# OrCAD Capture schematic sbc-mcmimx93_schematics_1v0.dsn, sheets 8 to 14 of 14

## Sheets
8 09 Gbe: size C; title: SBC-MCM93   09. Ethernet
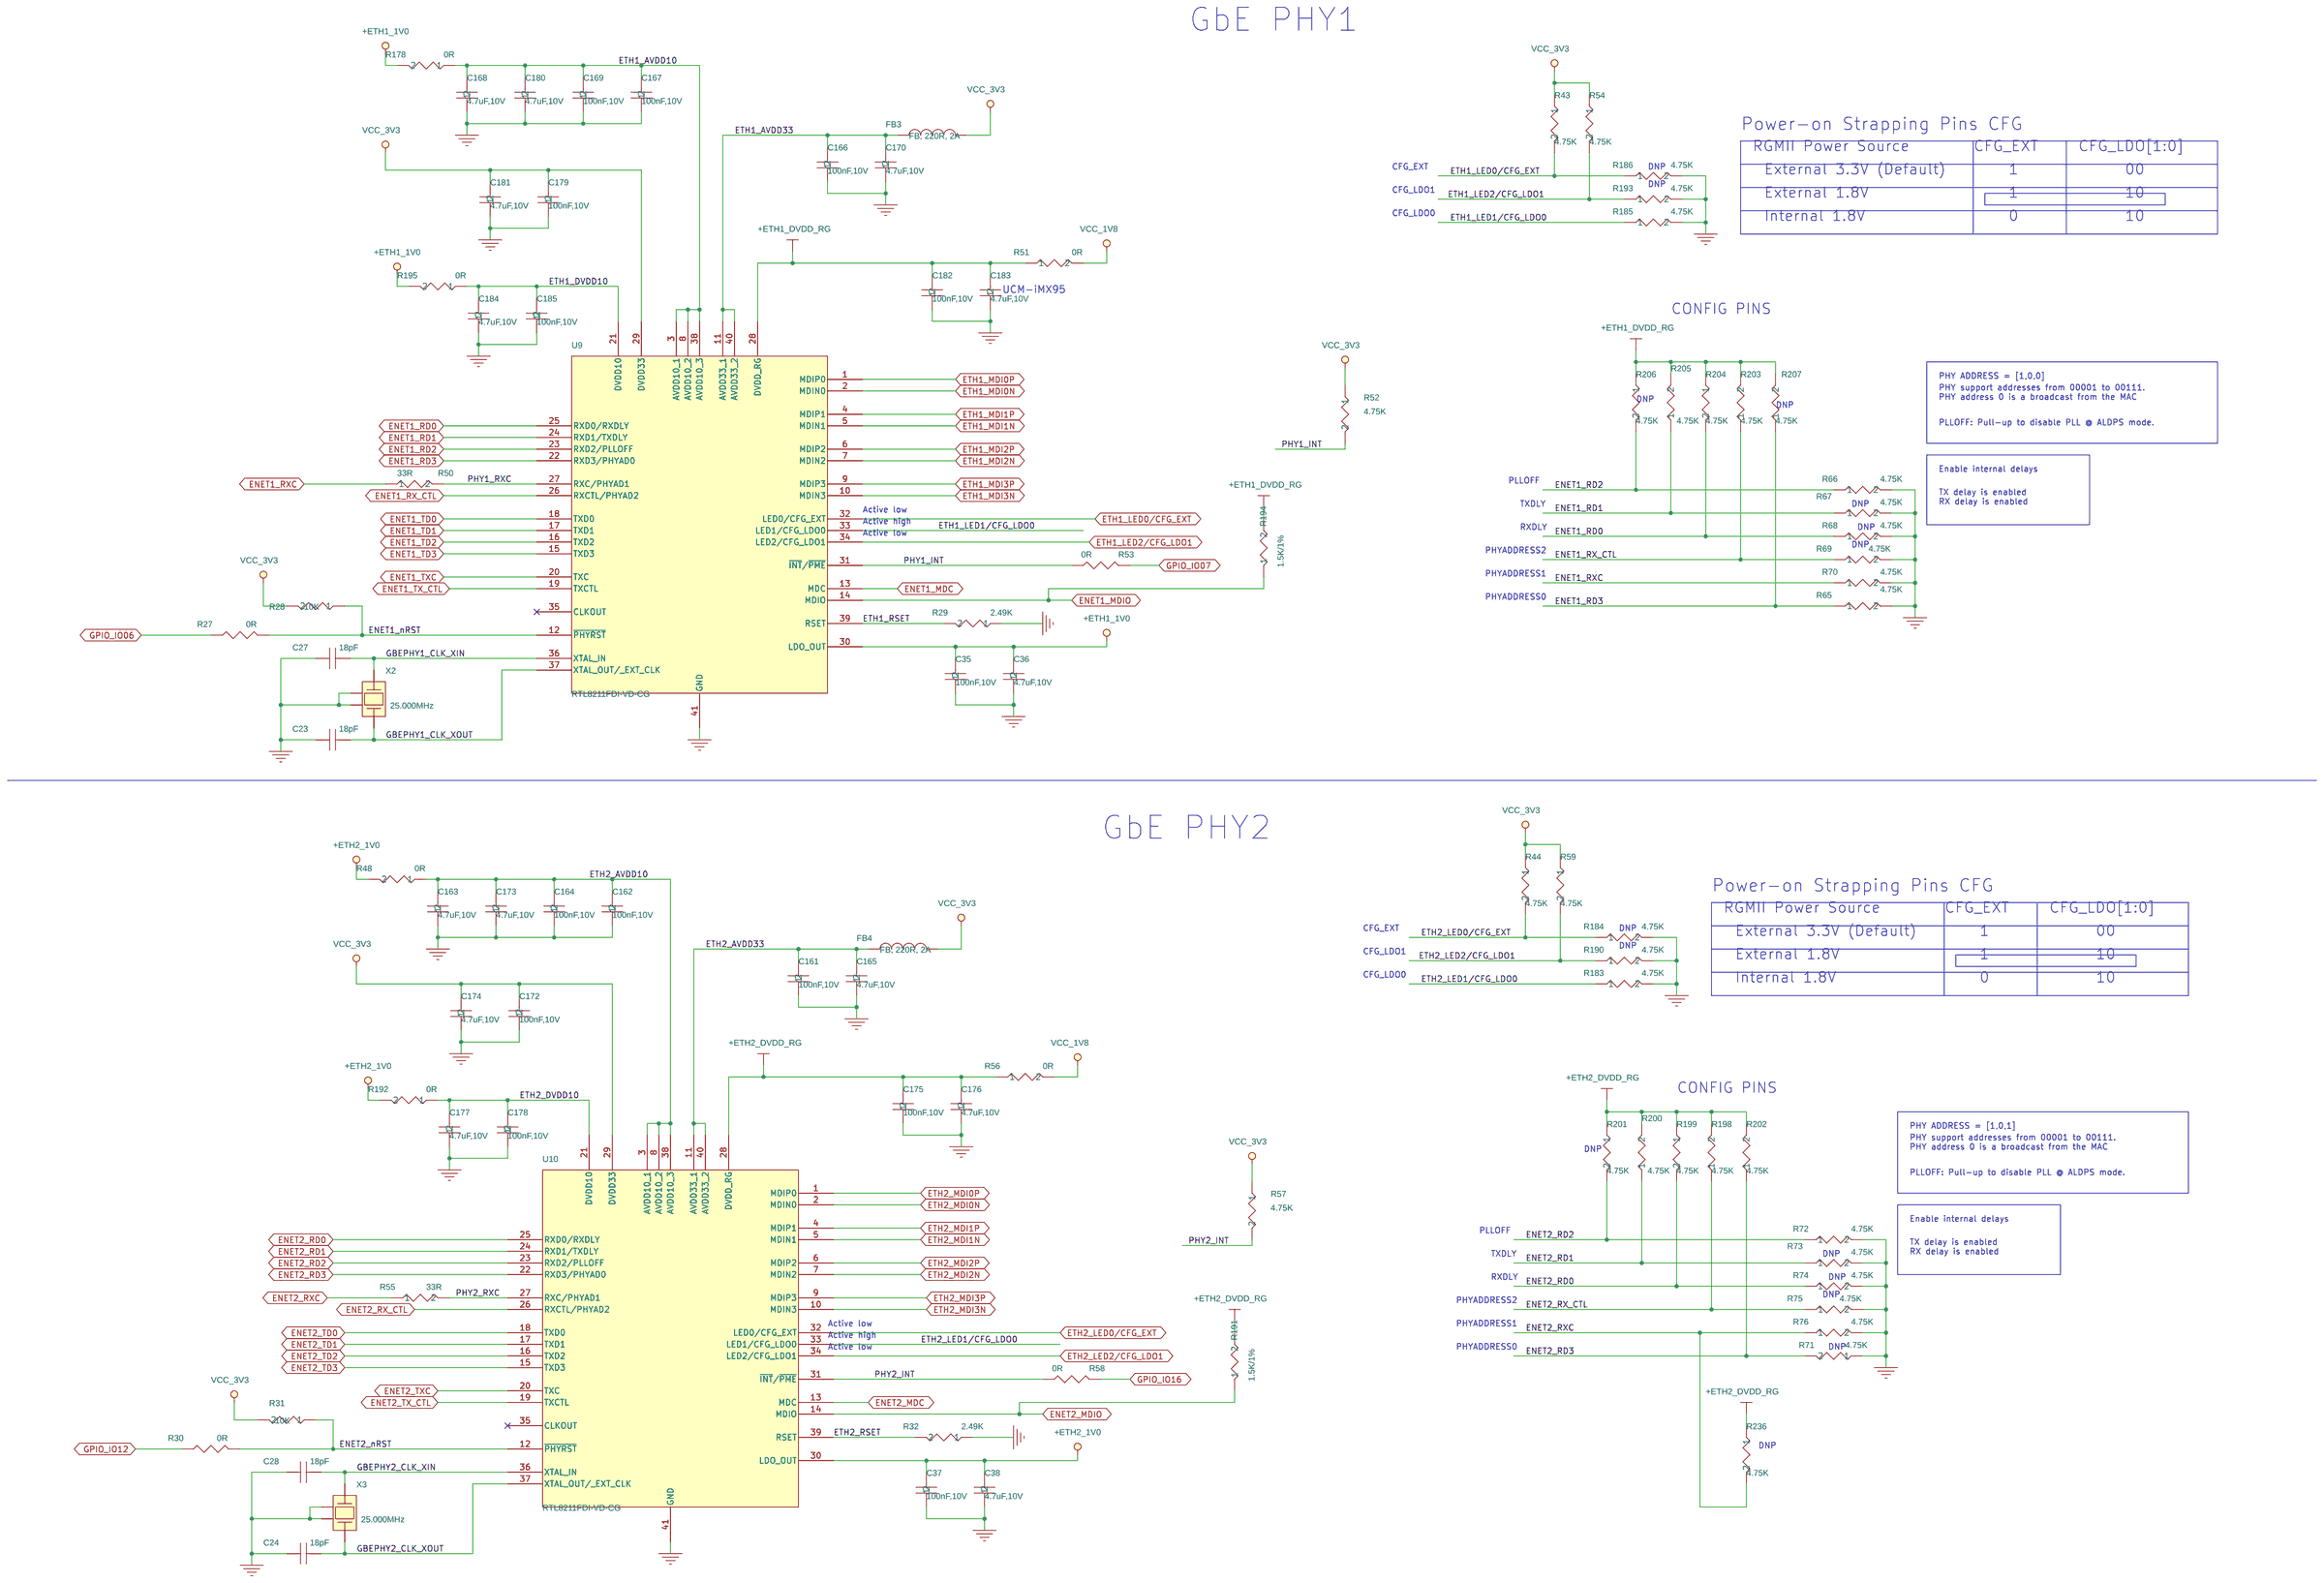
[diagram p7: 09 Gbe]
9 08 LVDS LCD: size B; title: SBC-MCM93   08. LVDS LCD
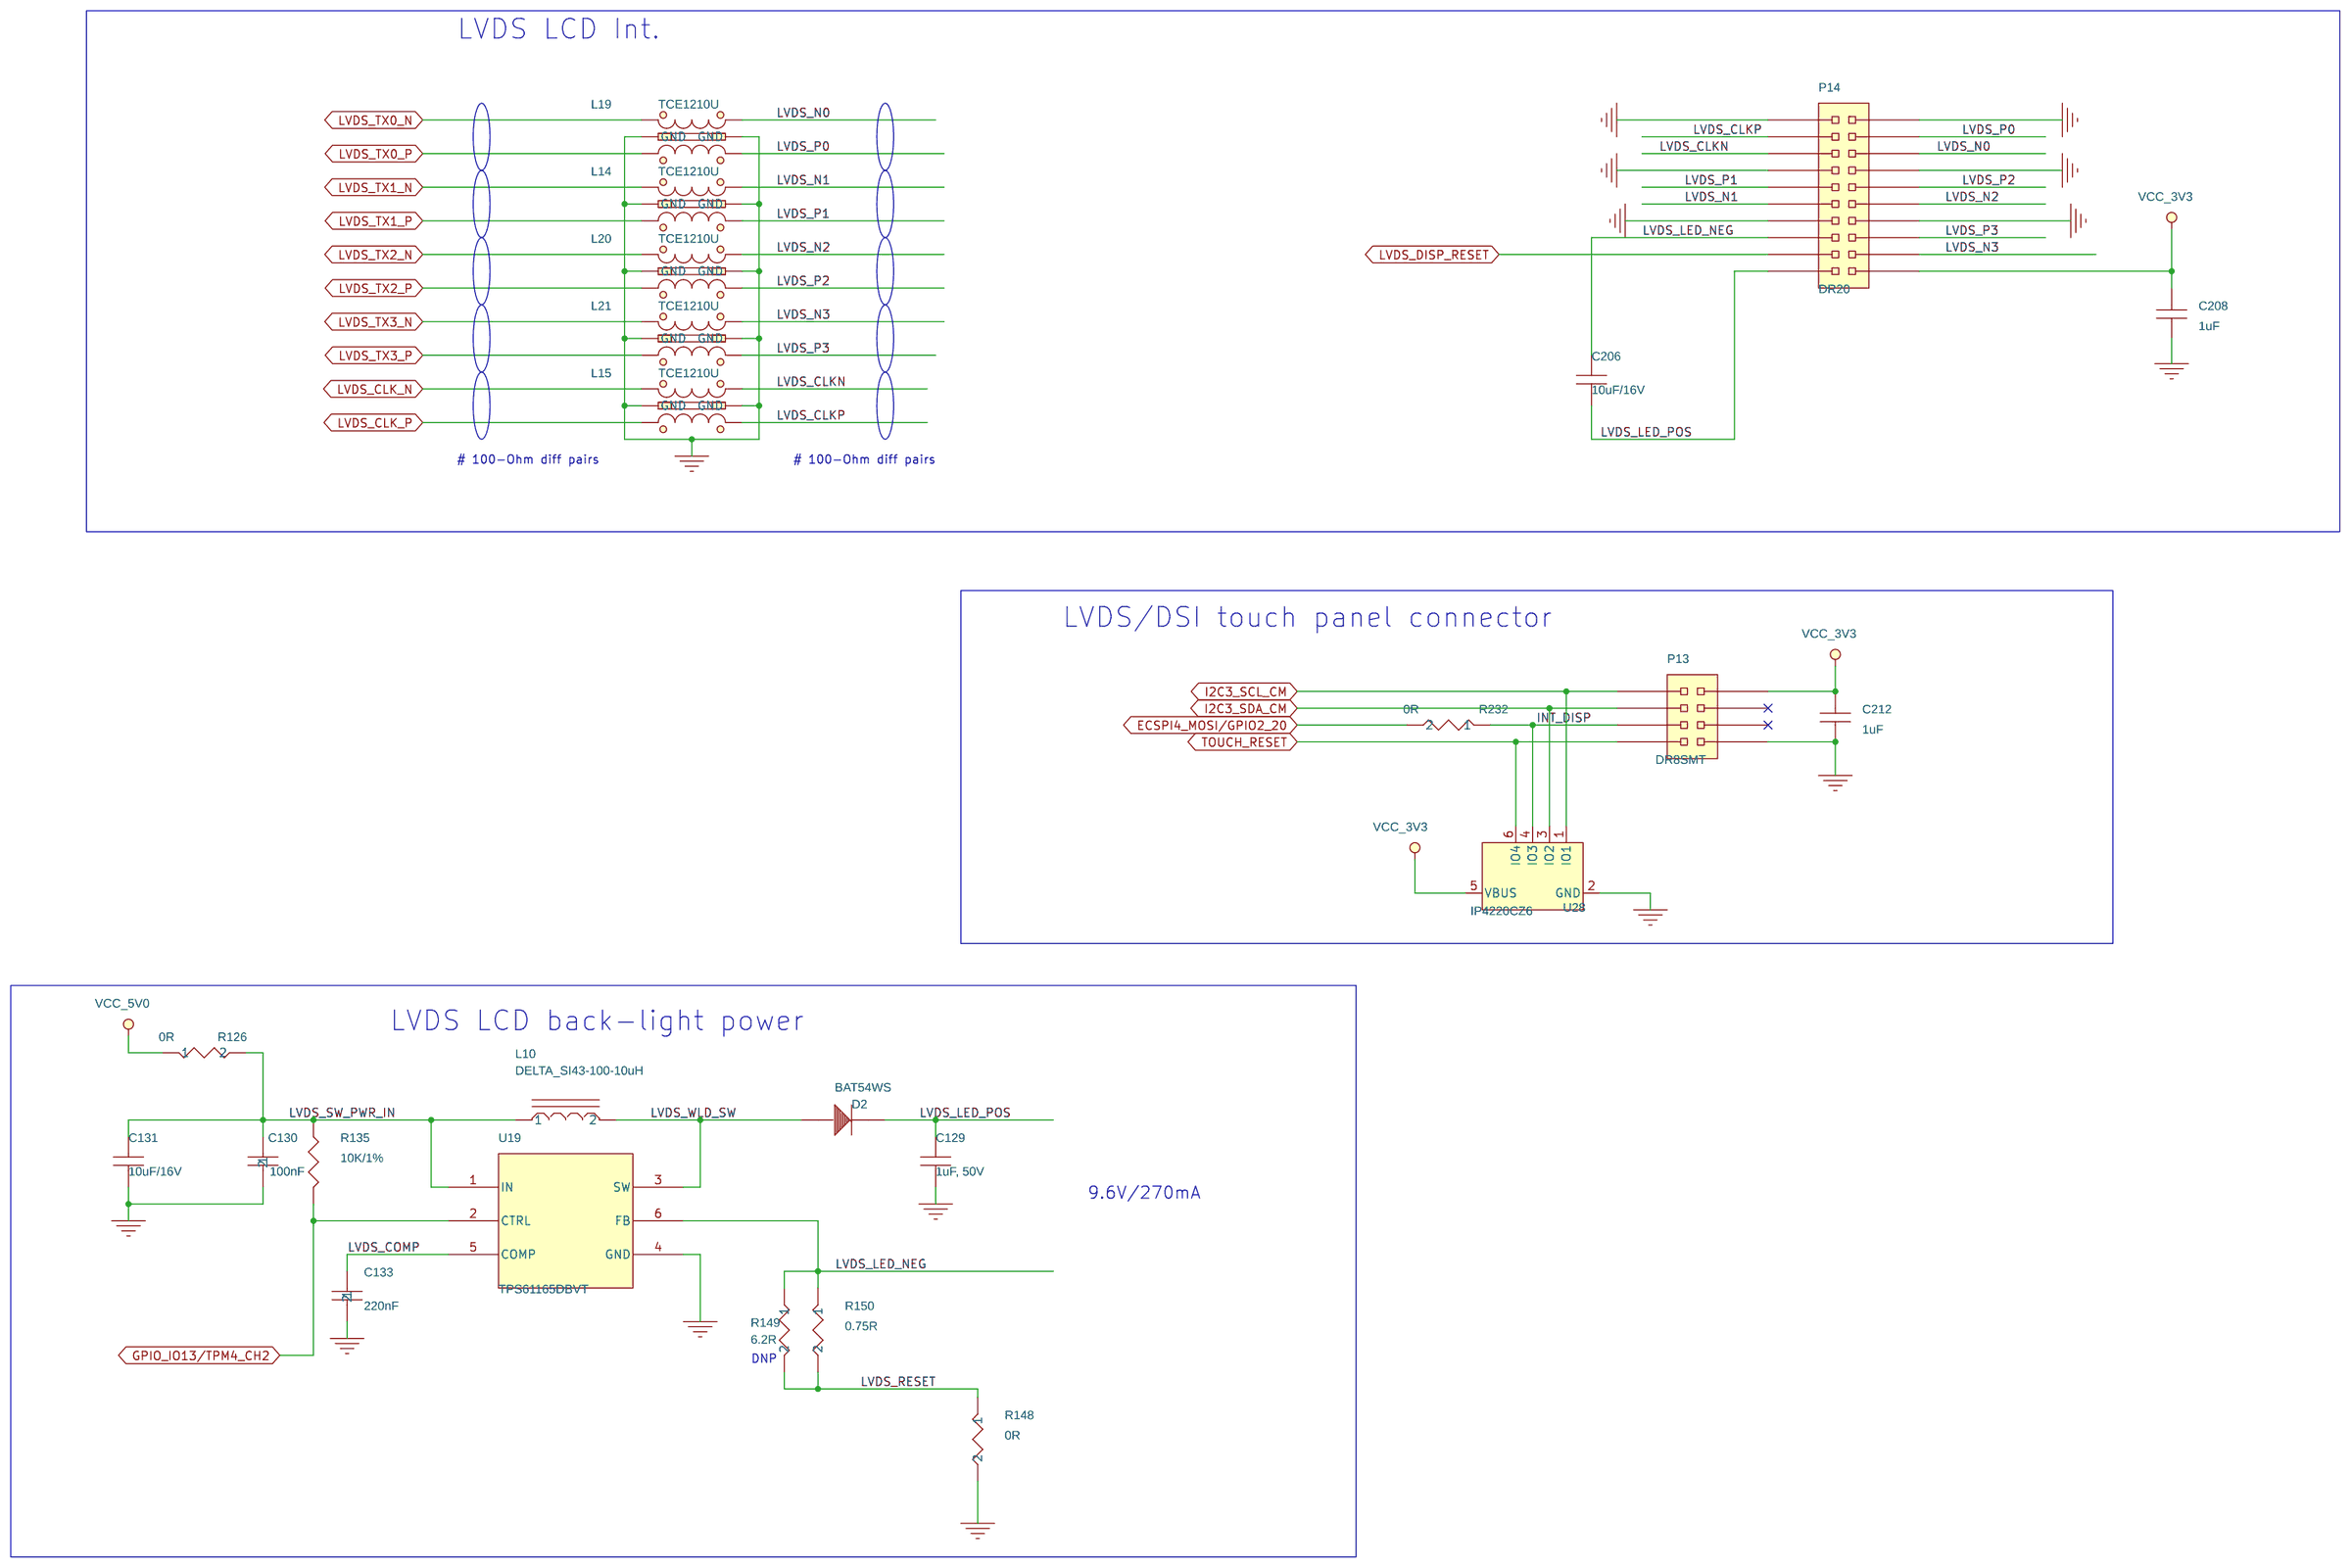
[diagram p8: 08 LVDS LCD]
10 11 Console, RS232, SD, miniPCIe: size C; title: SBC-MCM93    11. Console, RS232, SD, miniPCIe
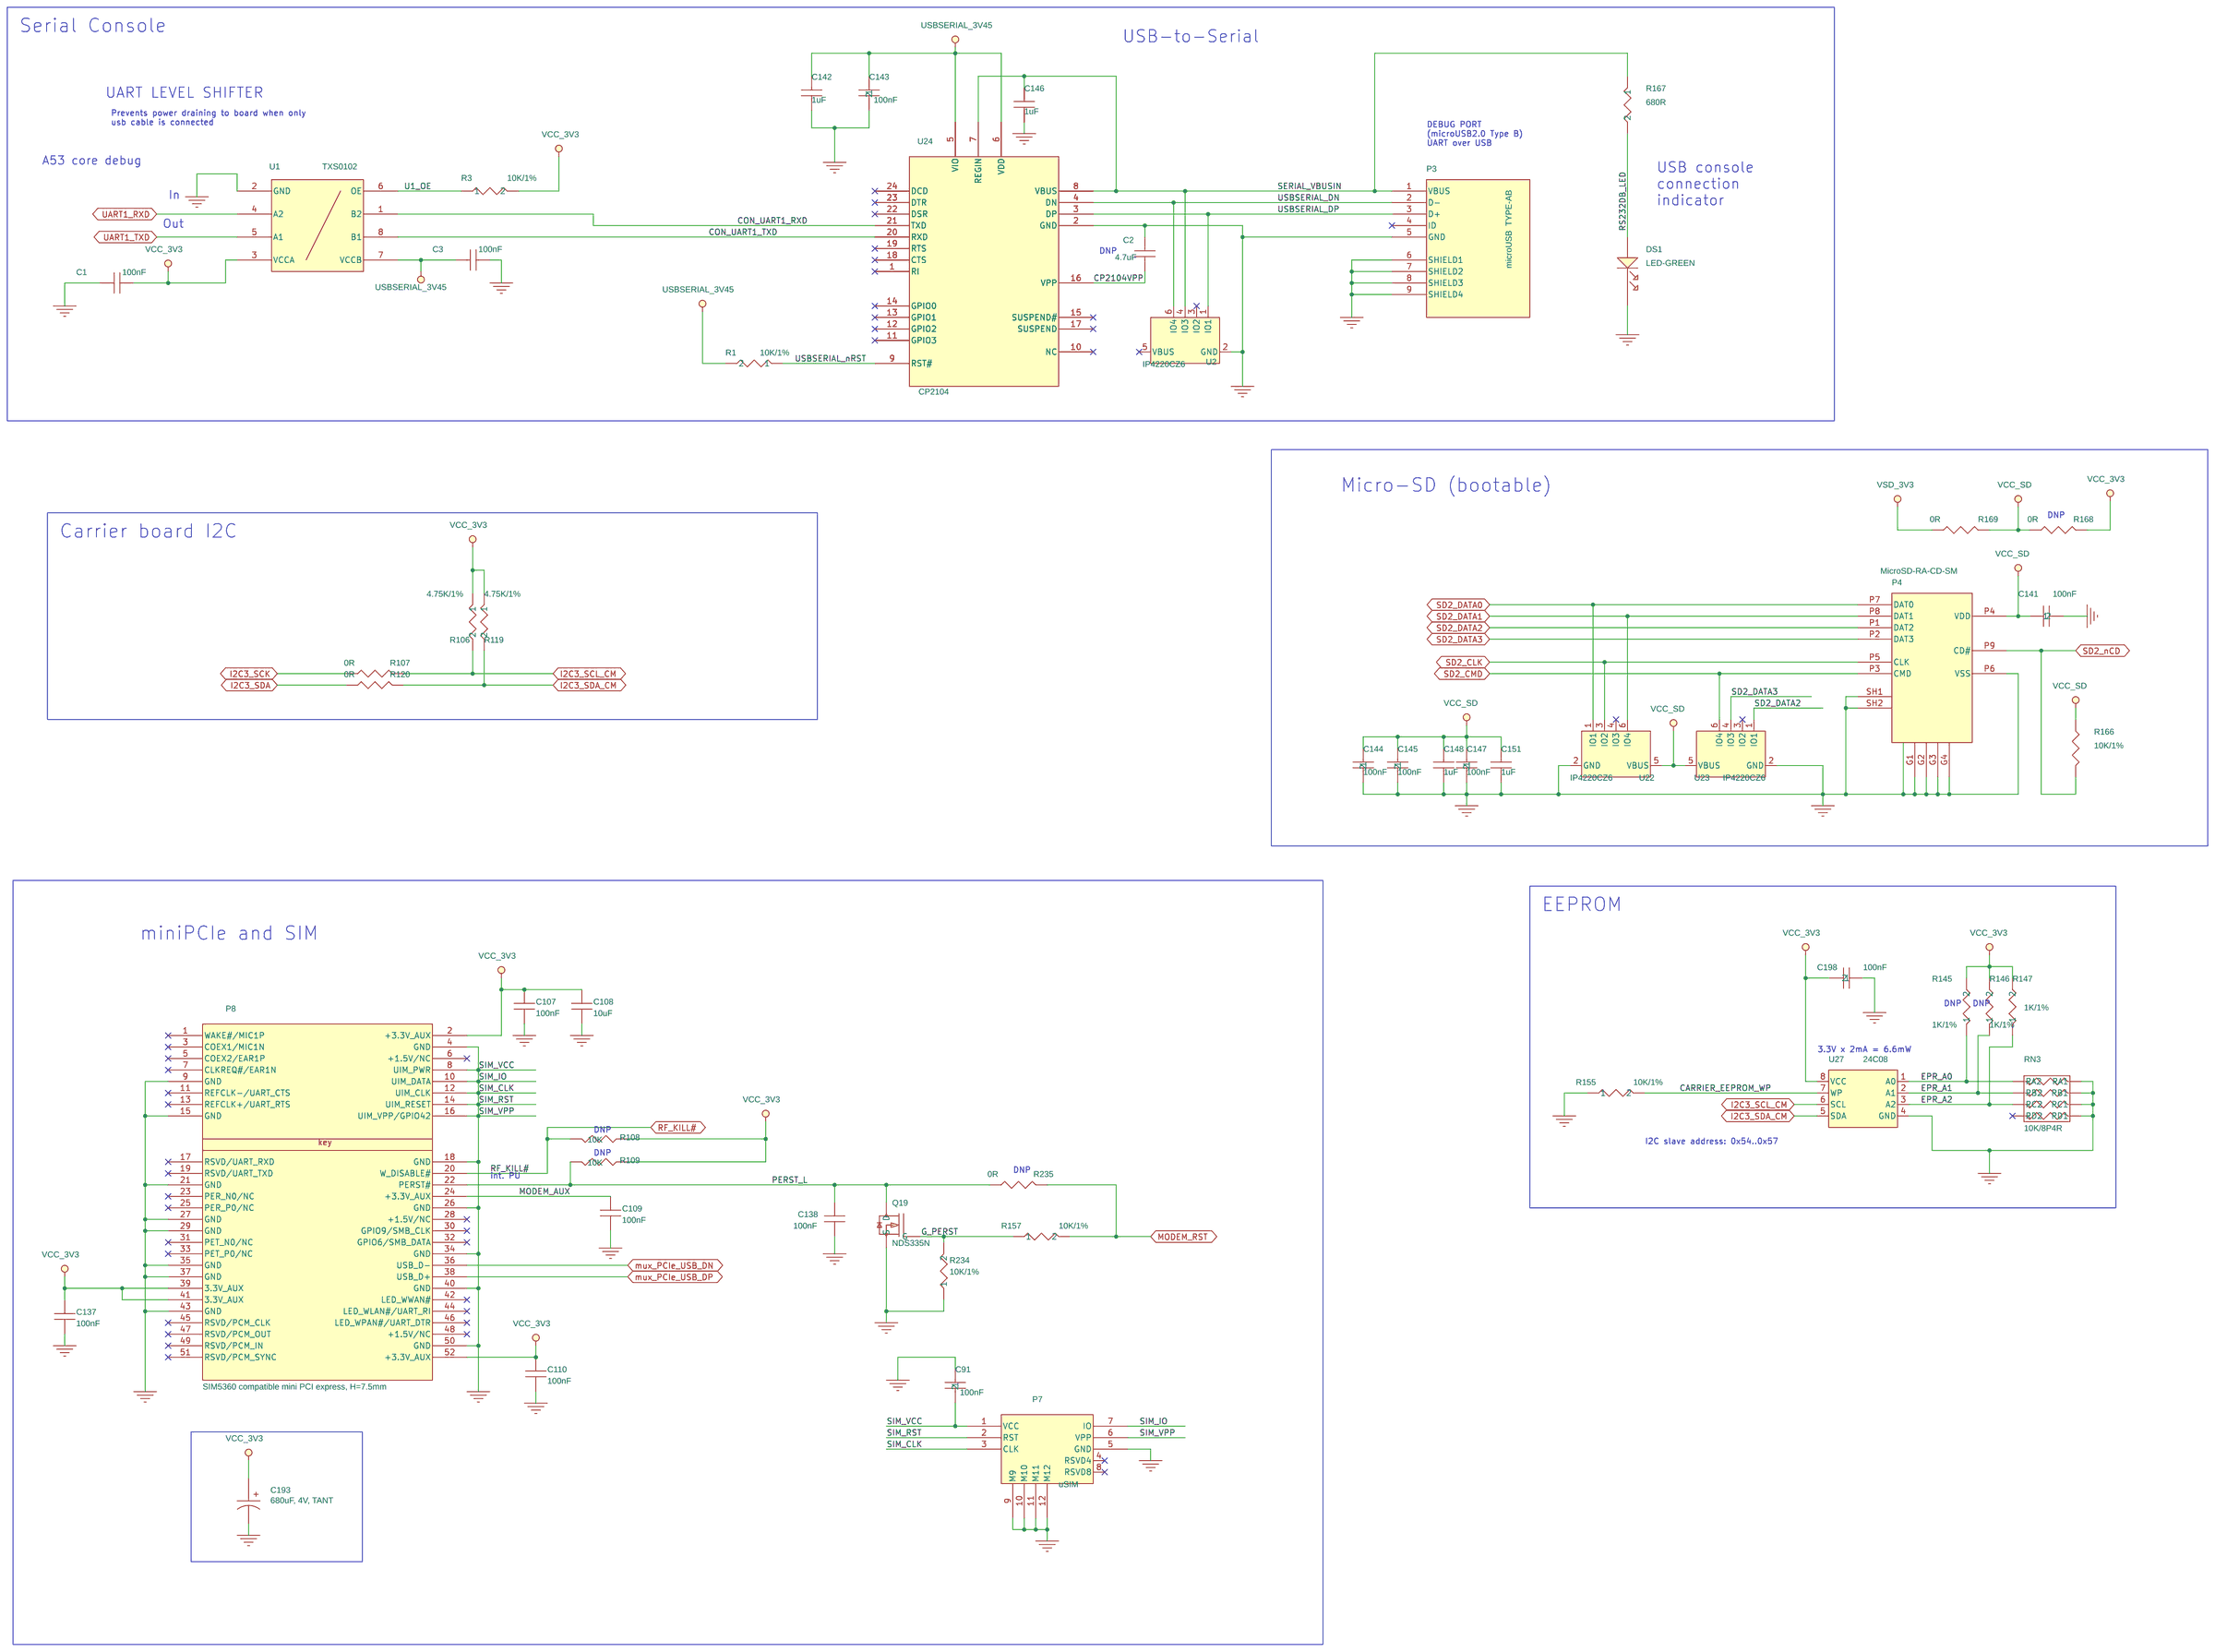
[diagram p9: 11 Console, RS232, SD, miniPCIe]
11 13 Power: size C; title: SBC-MCM93    13. Power
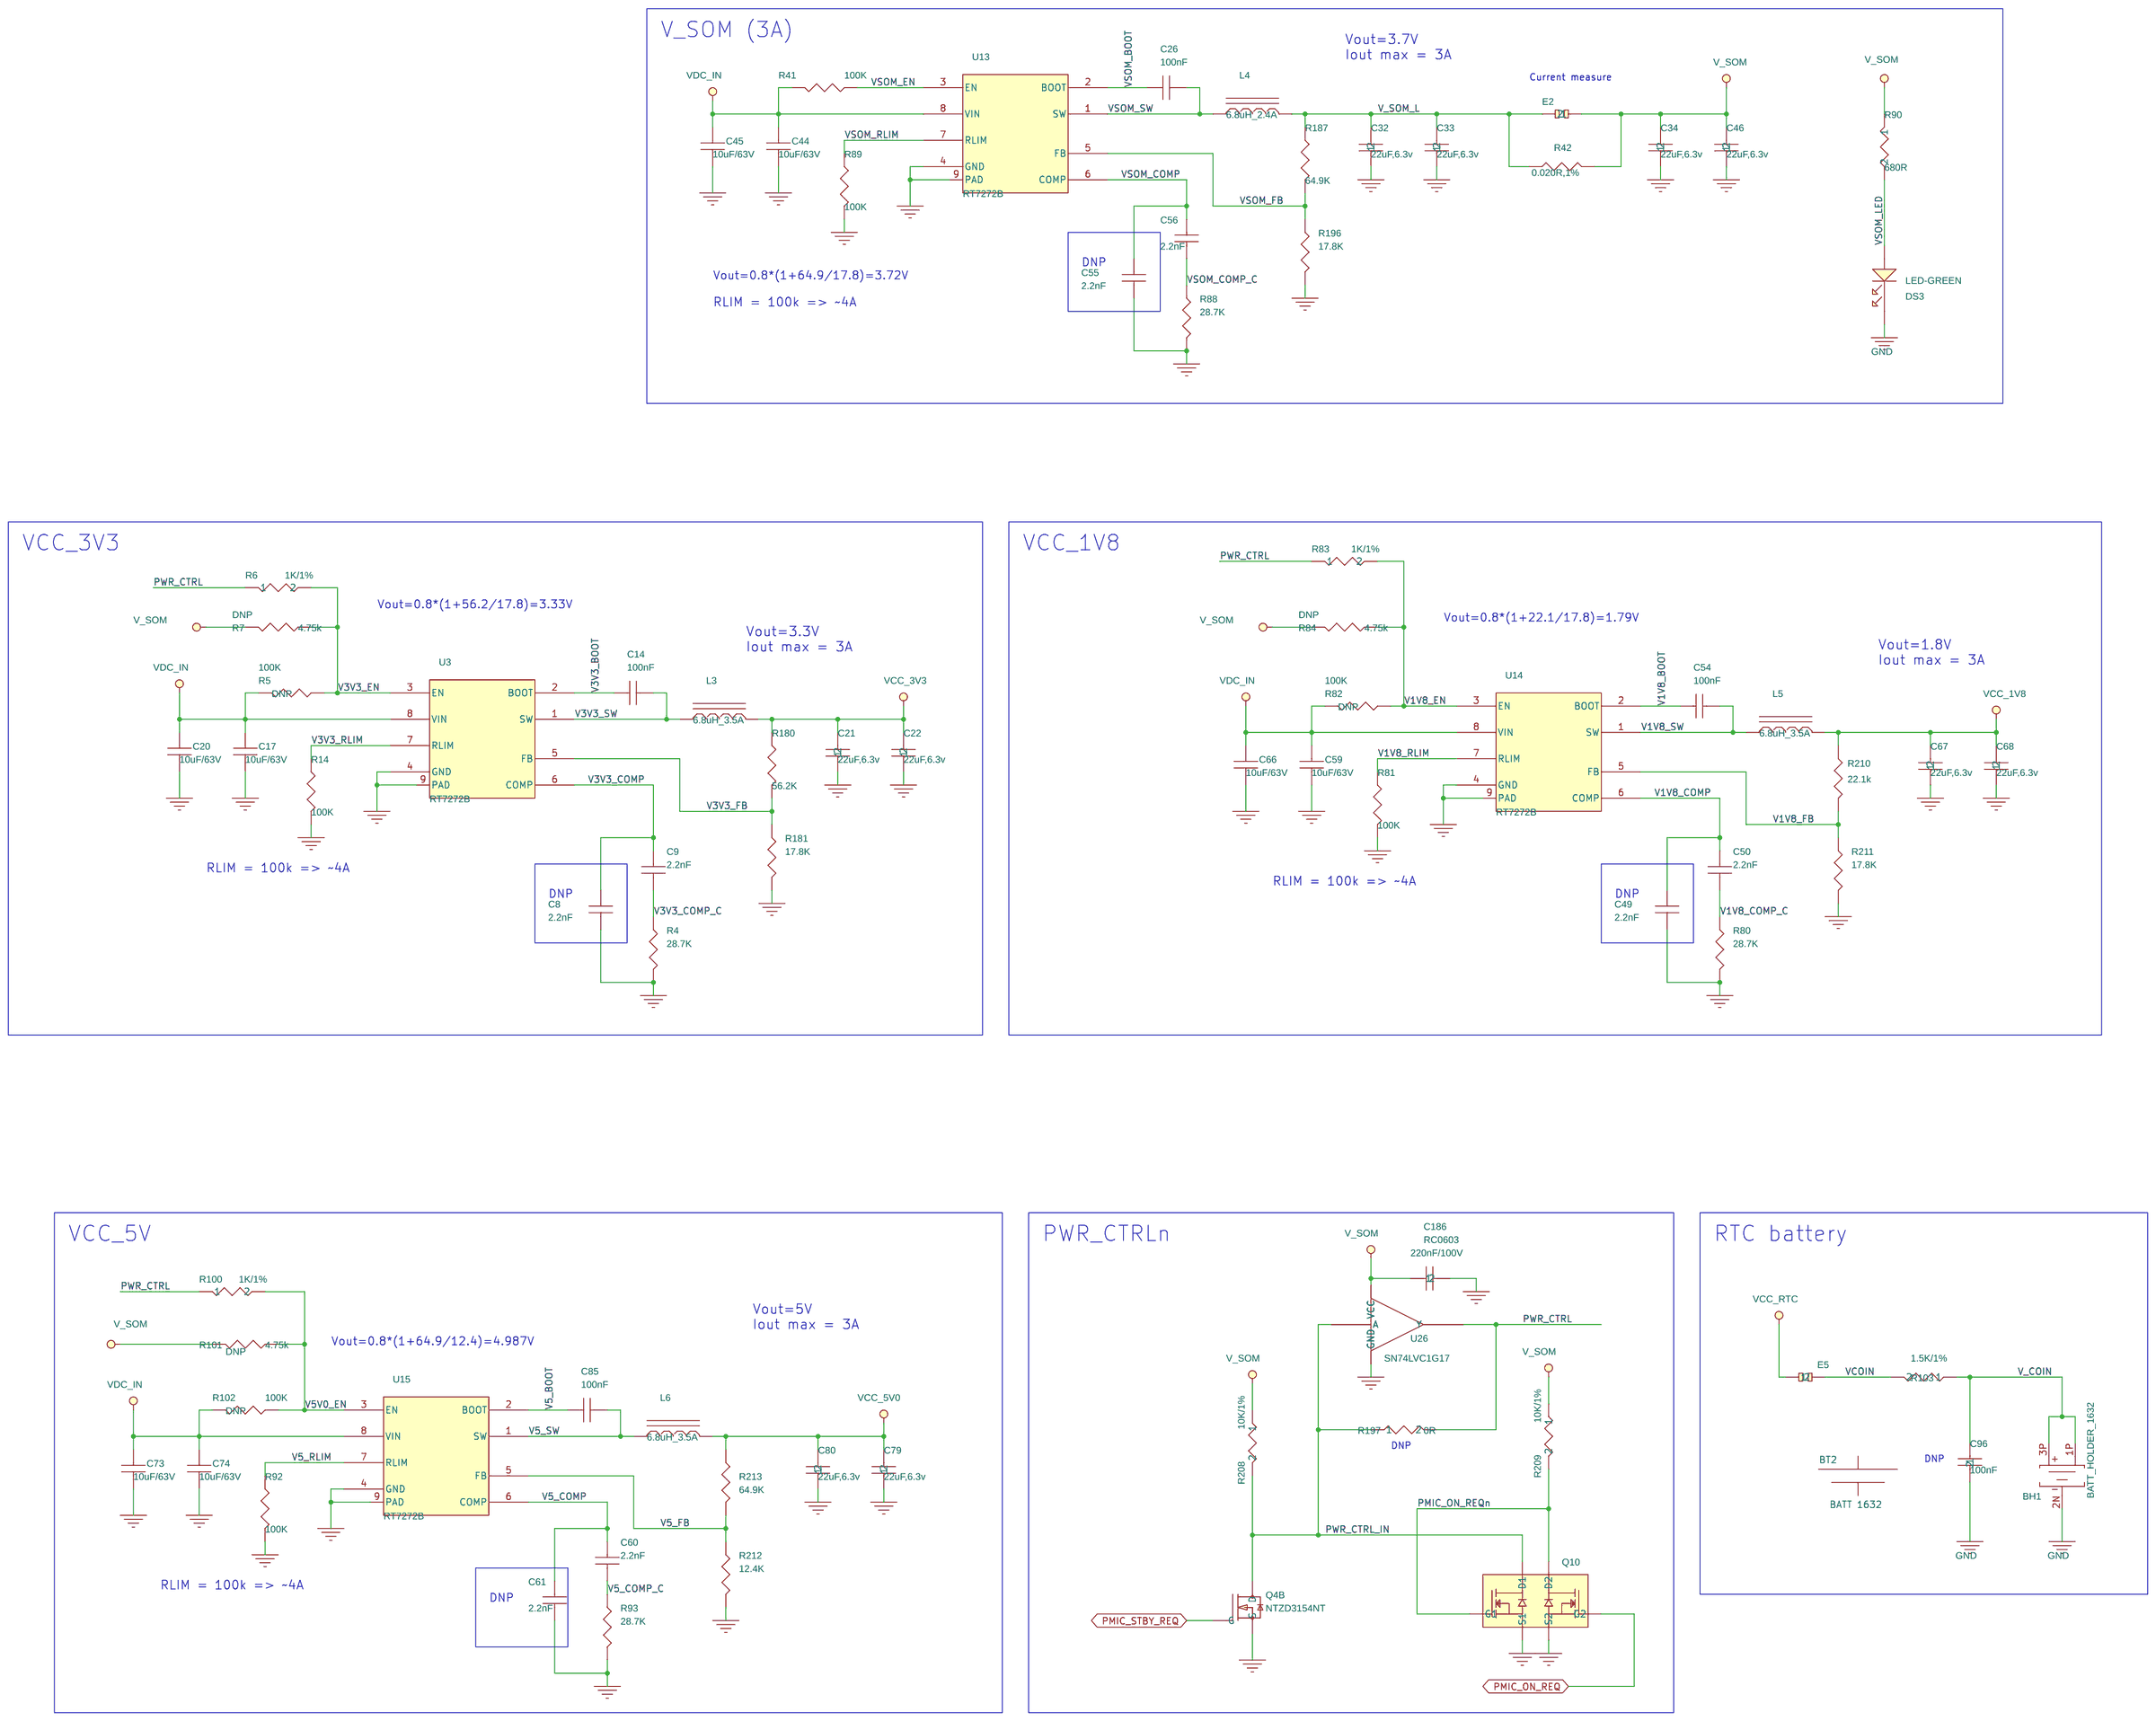
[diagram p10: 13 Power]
12 12 WIFI&Bluetooth: size C; title: SBC-MCM93     12. WLAN
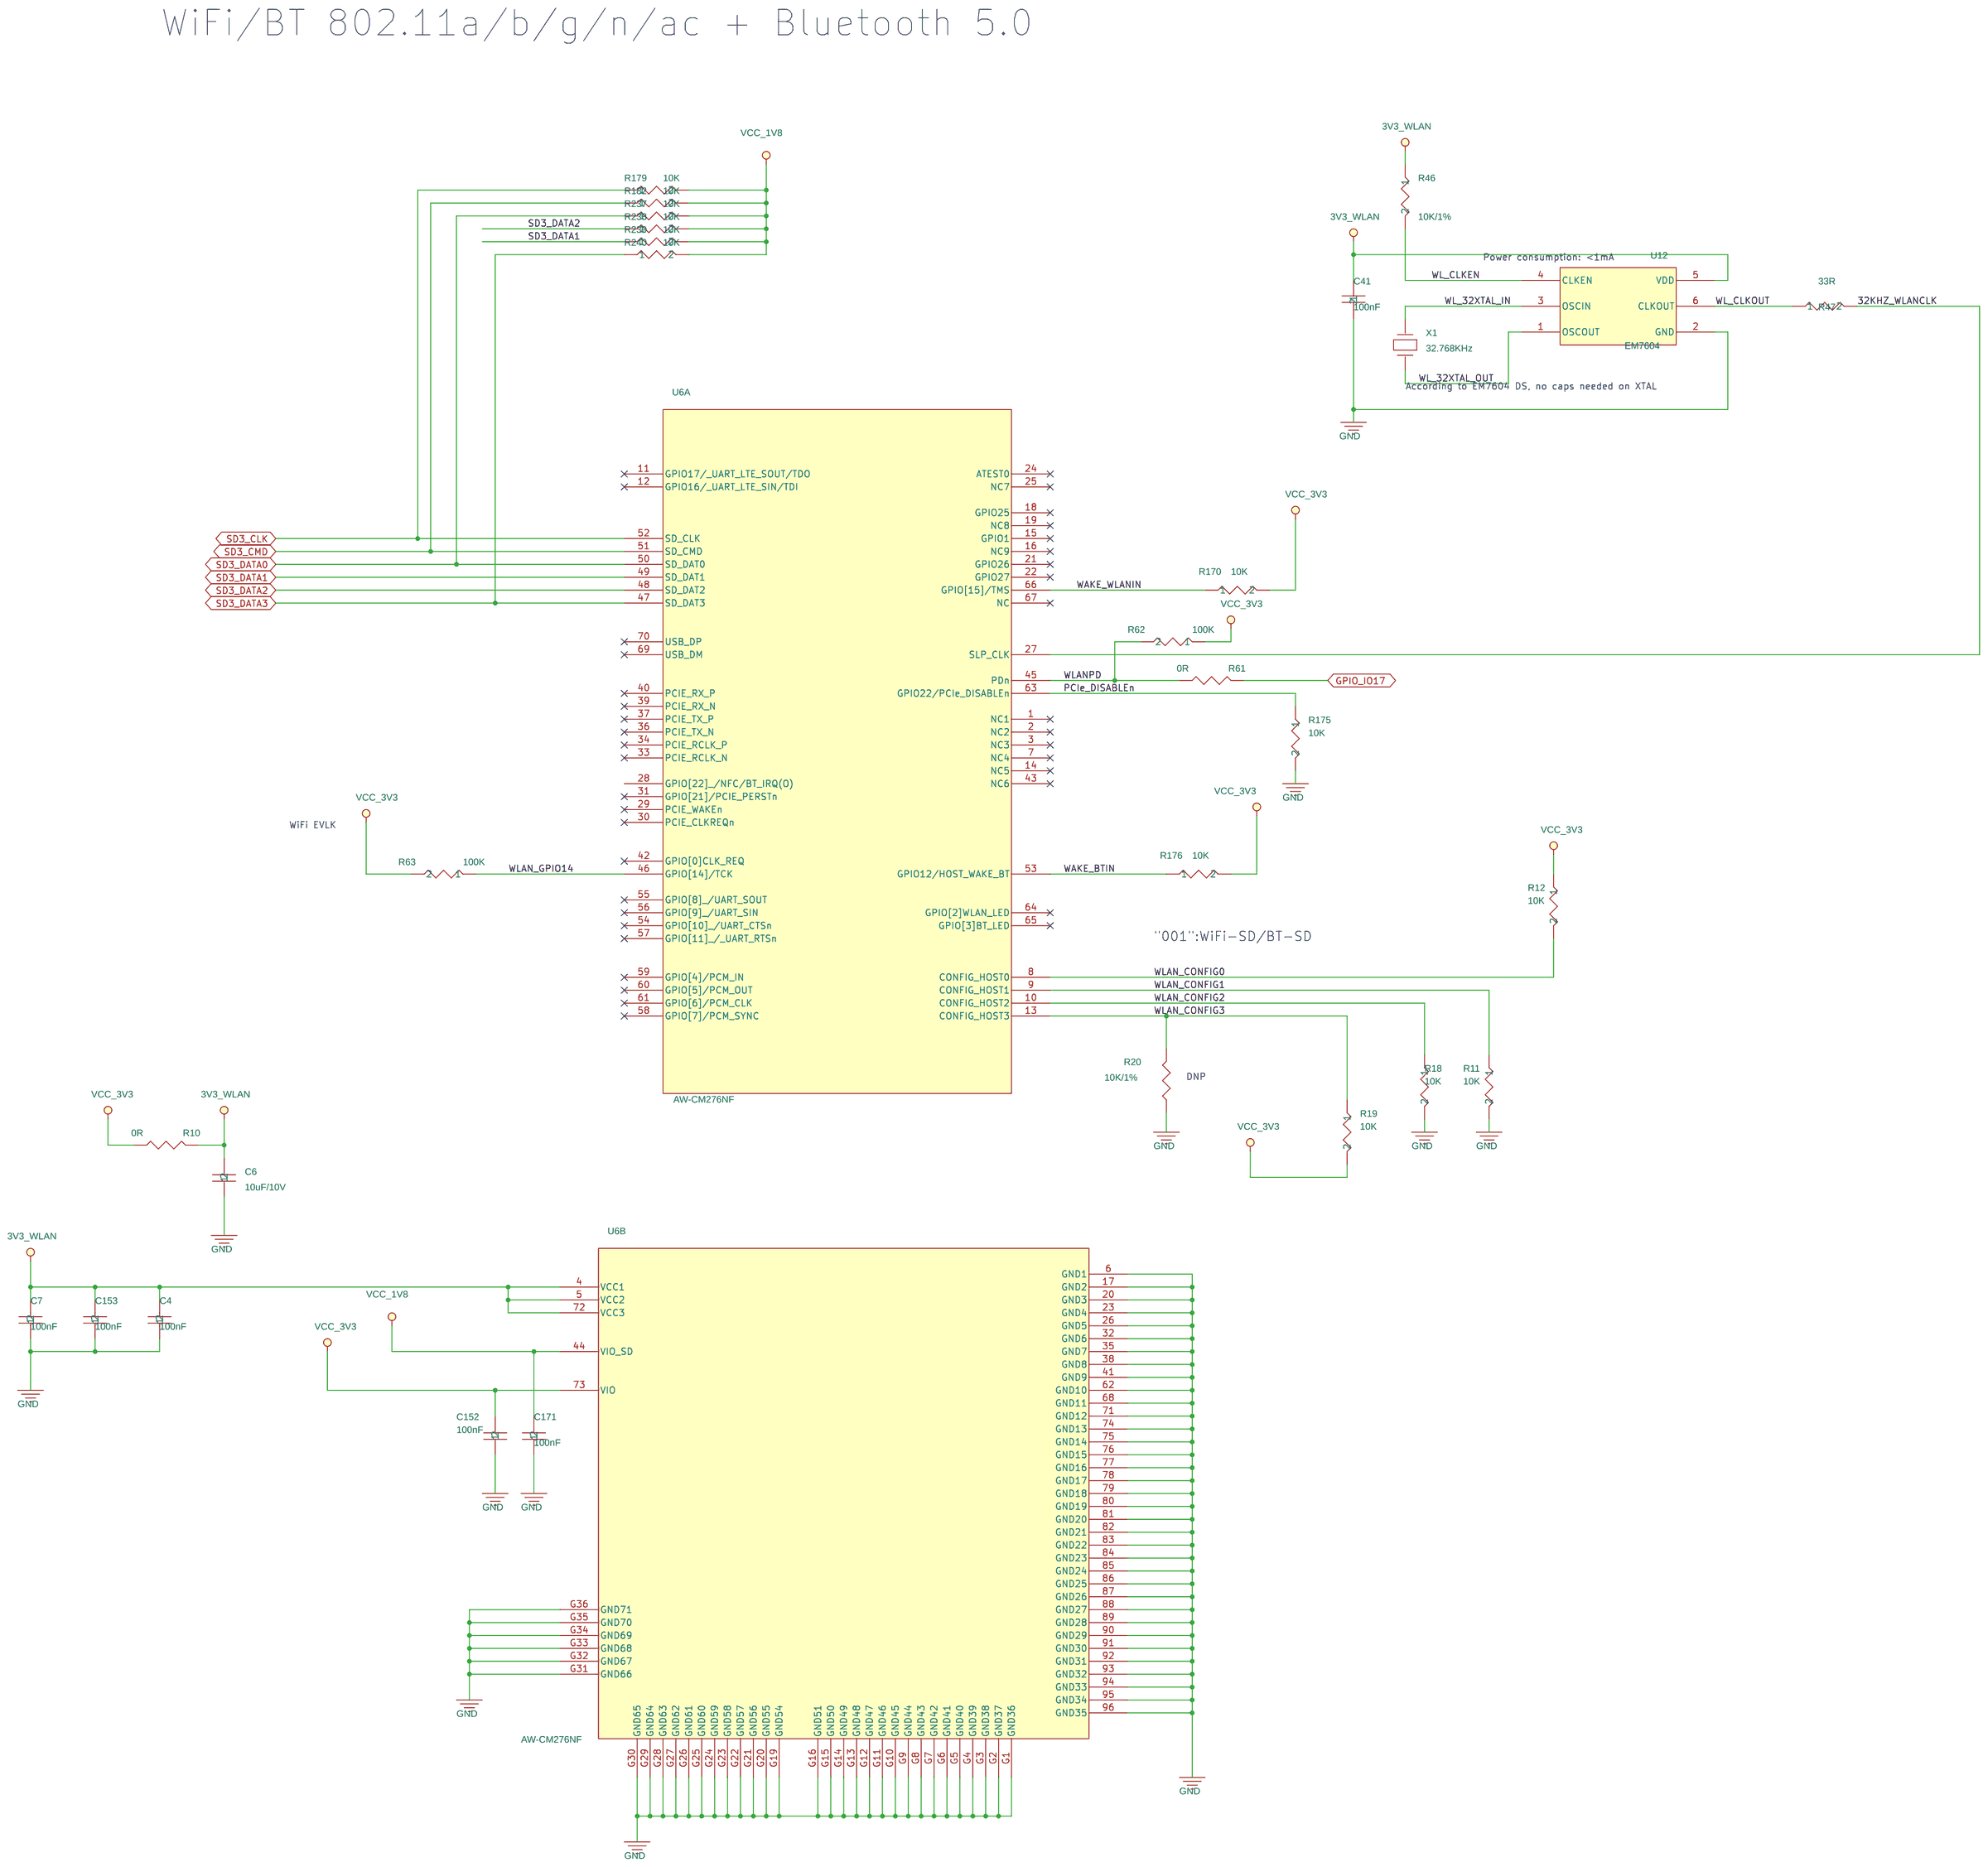
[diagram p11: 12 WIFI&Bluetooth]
13 14 Mechanical: size B; title: SBC-MCM93      14. Mechanical
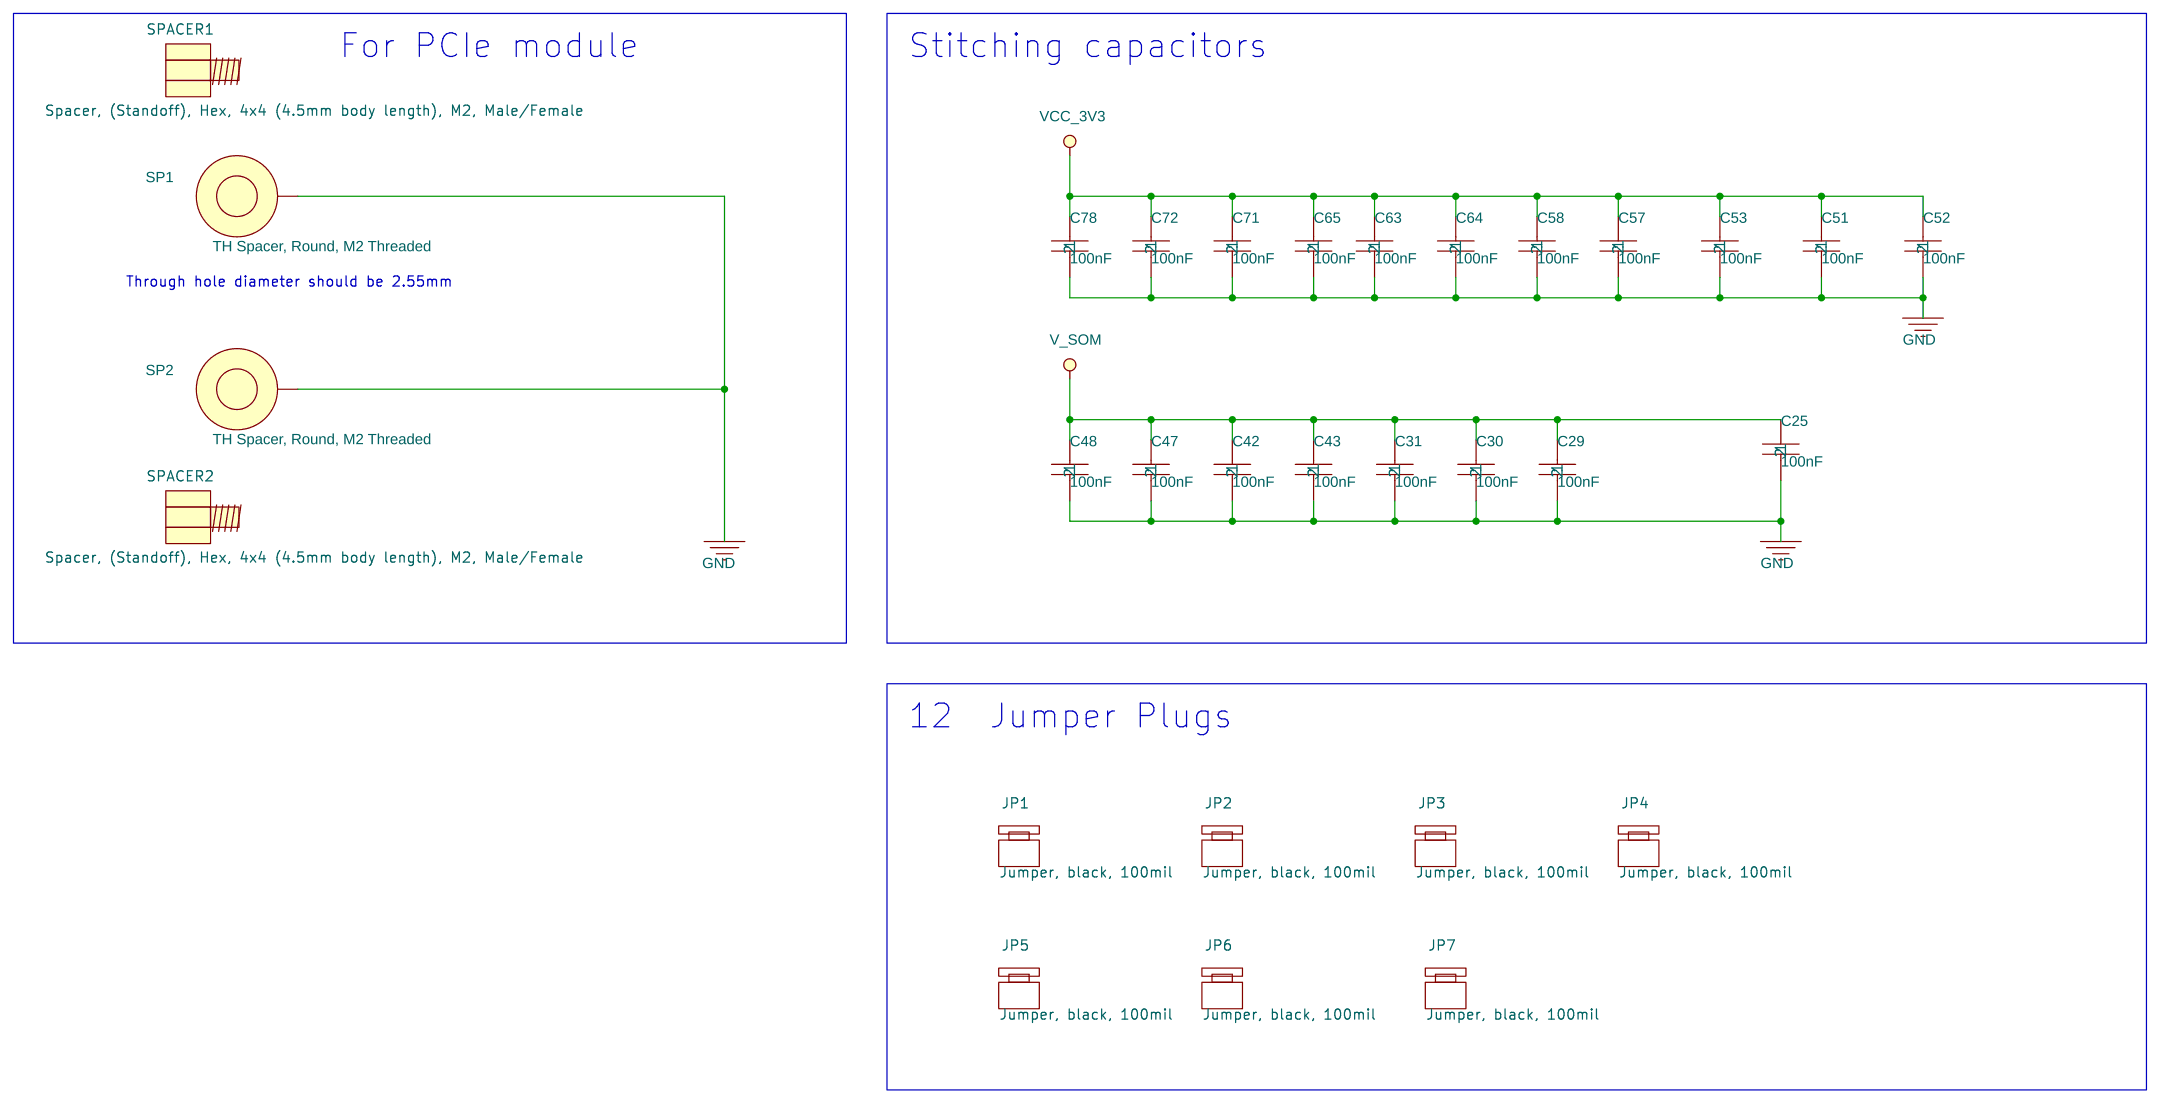
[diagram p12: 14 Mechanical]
14 06 Codec: size C; title: SBC-MCM93   06. Codec
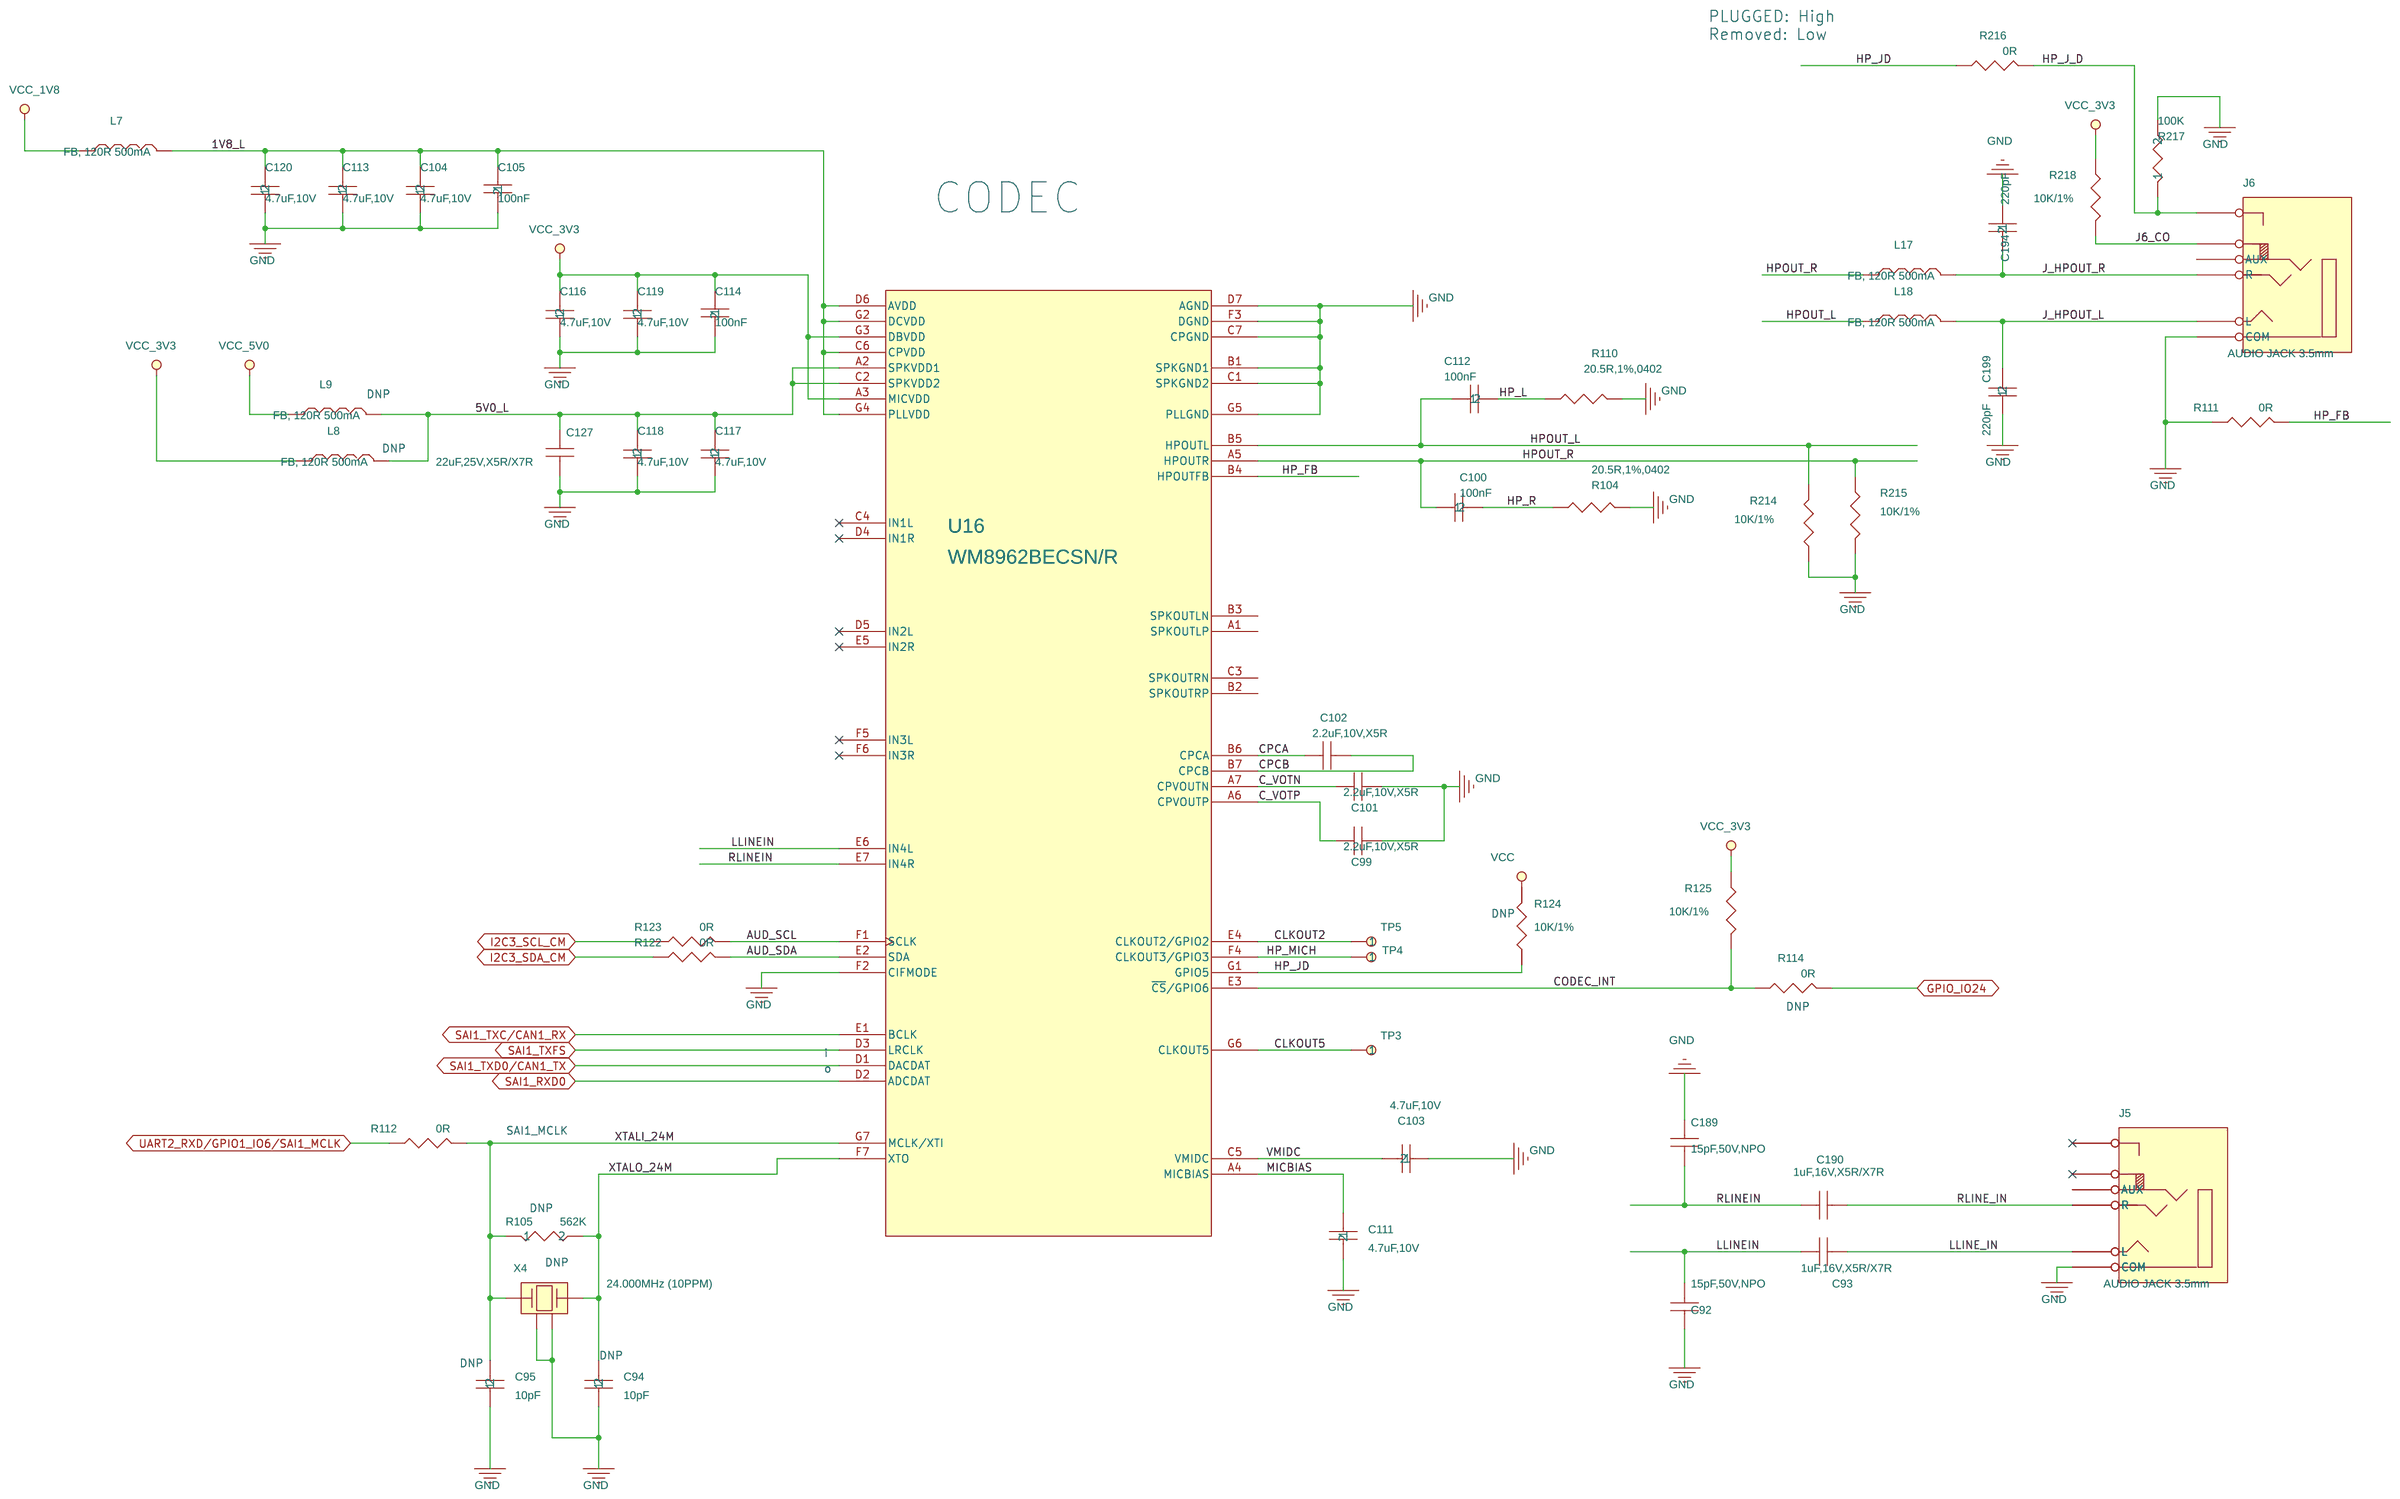
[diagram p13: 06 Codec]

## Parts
sheet 06 Codec
C92  15pF,50V,NPO  [RC0402]
C93  1uF,16V,X5R/X7R  [RC0402]
C94  10pF  [RC0402]
C95  10pF  [RC0402]
C99  2.2uF,10V,X5R  [RC0402]
C100  100nF  [RC0402]
C101  2.2uF,10V,X5R  [RC0402]
C102  2.2uF,10V,X5R  [RC0402]
C103  4.7uF,10V  [RC0402]
C104  4.7uF,10V  [RC0402]
C105  100nF  [RC0402]
C111  4.7uF,10V  [RC0402]
C112  100nF  [RC0402]
C113  4.7uF,10V  [RC0402]
C114  100nF  [RC0402]
C116  4.7uF,10V  [RC0402]
C117  4.7uF,10V  [RC0402]
C118  4.7uF,10V  [RC0402]
C119  4.7uF,10V  [RC0402]
C120  4.7uF,10V  [RC0402]
C127  22uF,25V,X5R/X7R  [C0805]
C189  15pF,50V,NPO  [RC0402]
C190  1uF,16V,X5R/X7R  [RC0402]
C194  220pF  [RC0603]
C199  220pF  [RC0603]
J5  AUDIO JACK 3.5mm  [AJ35-4P-SW-SM]
J6  AUDIO JACK 3.5mm  [AJ35-4P-SW-SM]
L7  FB, 120R 500mA  [FB0402]
L8  FB, 120R 500mA  [FB0402]
L9  FB, 120R 500mA  [FB0402]
L17  FB, 120R 500mA  [FB0402]
L18  FB, 120R 500mA  [FB0402]
R104  20.5R,1%,0402  [RC0402]
R105  562K  [RC0402]
R110  20.5R,1%,0402  [RC0402]
R111  0R  [RC0402]
R112  0R  [RC0402]
R114  0R  [RC0402]
R122  0R  [RC0402]
R123  0R  [RC0402]
R124  10K/1%  [RC0402]
R125  10K/1%  [RC0402]
R214  10K/1%  [RC0402]
R215  10K/1%  [RC0402]
R216  0R  [RC0402]
R217  100K  [RC0402]
R218  10K/1%  [RC0402]
TP3  TESTPOINT SMT  [TESTPOINT]
TP4  TESTPOINT SMT  [TESTPOINT]
TP5  TESTPOINT SMT  [TESTPOINT]
U16  WM8962BECSN/R  [BGA49_0P5_3P62X4]
X4  24.000MHz (10PPM)  [OSC3225]
sheet 08 LVDS LCD
C129  1uF, 50V  [RC0603]
C130  100nF  [RC0402]
C131  10uF/16V  [RC0603]
C133  220nF  [RC0402]
C206  10uF/16V  [RC0603]
C208  1uF  [RC0402]
C212  1uF  [RC0402]
D2  BAT54WS  [SOD-323]
L10  DELTA_SI43-100-10uH  [IND4x4x2_5]
L14  TCE1210U  [EMI1012-ESD]
L15  TCE1210U  [EMI1012-ESD]
L19  TCE1210U  [EMI1012-ESD]
L20  TCE1210U  [EMI1012-ESD]
L21  TCE1210U  [EMI1012-ESD]
P13  DR8SMT  [2X4SMHDR]
P14  DR20  [2X12THHDR]
R126  0R  [RC1206]
R135  10K/1%  [RC0402]
R148  0R  [RC0402]
R149  6.2R  [RC0402]
R150  0.75R  [RC0402]
R232  0R  [RC0402]
U19  TPS61165DBVT  [SOT23-6]
U28  IP4220CZ6  [SOT23-6L]
sheet 09 Gbe
C23  18pF  [RC0402]
C24  18pF  [RC0402]
C27  18pF  [RC0402]
C28  18pF  [RC0402]
C35  100nF,10V  [RC0402]
C36  4.7uF,10V  [RC0402]
C37  100nF,10V  [RC0402]
C38  4.7uF,10V  [RC0402]
C161  100nF,10V  [RC0402]
C162  100nF,10V  [RC0402]
C163  4.7uF,10V  [RC0402]
C164  100nF,10V  [RC0402]
C165  4.7uF,10V  [RC0402]
C166  100nF,10V  [RC0402]
C167  100nF,10V  [RC0402]
C168  4.7uF,10V  [RC0402]
C169  100nF,10V  [RC0402]
C170  4.7uF,10V  [RC0402]
C172  100nF,10V  [RC0402]
C173  4.7uF,10V  [RC0402]
C174  4.7uF,10V  [RC0402]
C175  100nF,10V  [RC0402]
C176  4.7uF,10V  [RC0402]
C177  4.7uF,10V  [RC0402]
C178  100nF,10V  [RC0402]
C179  100nF,10V  [RC0402]
C180  4.7uF,10V  [RC0402]
C181  4.7uF,10V  [RC0402]
C182  100nF,10V  [RC0402]
C183  4.7uF,10V  [RC0402]
C184  4.7uF,10V  [RC0402]
C185  100nF,10V  [RC0402]
FB3  FB, 220R, 2A  [FB0402]
FB4  FB, 220R, 2A  [FB0402]
R27  0R  [RC0402]
R28  10K  [RC0402]
R29  2.49K  [RC0402]
R30  0R  [RC0402]
R31  10K  [RC0402]
R32  2.49K  [RC0402]
R43  4.75K  [RC0402]
R44  4.75K  [RC0402]
R48  0R  [RC0402]
R50  33R  [RC0402]
R51  0R  [RC0402]
R52  4.75K  [RC0402]
R53  0R  [RC0402]
R54  4.75K  [RC0402]
R55  33R  [RC0402]
R56  0R  [RC0402]
R57  4.75K  [RC0402]
R58  0R  [RC0402]
R59  4.75K  [RC0402]
R65  4.75K  [RC0402]
R66  4.75K  [RC0402]
R67  4.75K  [RC0402]
R68  4.75K  [RC0402]
R69  4.75K  [RC0402]
R70  4.75K  [RC0402]
R71  4.75K  [RC0402]
R72  4.75K  [RC0402]
R73  4.75K  [RC0402]
R74  4.75K  [RC0402]
R75  4.75K  [RC0402]
R76  4.75K  [RC0402]
R178  0R  [RC0402]
R183  4.75K  [RC0402]
R184  4.75K  [RC0402]
R185  4.75K  [RC0402]
R186  4.75K  [RC0402]
R190  4.75K  [RC0402]
R191  1.5K/1%  [RC0402]
R192  0R  [RC0402]
R193  4.75K  [RC0402]
R194  1.5K/1%  [RC0402]
R195  0R  [RC0402]
R198  4.75K  [RC0402]
R199  4.75K  [RC0402]
R200  4.75K  [RC0402]
R201  4.75K  [RC0402]
R202  4.75K  [RC0402]
R203  4.75K  [RC0402]
R204  4.75K  [RC0402]
R205  4.75K  [RC0402]
R206  4.75K  [RC0402]
R207  4.75K  [RC0402]
R236  4.75K  [RC0402]
U9  RTL8211FDI-VD-CG  [qfn40_0p4_5x5mm]
U10  RTL8211FDI-VD-CG  [qfn40_0p4_5x5mm]
X2  25.000MHz  [OSC3225]
X3  25.000MHz  [OSC3225]
sheet 11 Console, RS232, SD, miniPCIe
C1  100nF  [RC0402]
C2  4.7uF  [C0603-08]
C3  100nF  [RC0402]
C91  100nF  [RC0402]
C107  100nF  [RC0402]
C108  10uF  [RC0603]
C109  100nF  [RC0402]
C110  100nF  [RC0402]
C137  100nF  [RC0402]
C138  100nF  [RC0402]
C141  100nF  [RC0402]
C142  1uF  [RC0402]
C143  100nF  [RC0402]
C144  100nF  [RC0402]
C145  100nF  [RC0402]
C146  1uF  [RC0402]
C147  100nF  [RC0402]
C148  1uF  [RC0402]
C151  1uF  [RC0402]
C193  680uF, 4V, TANT  [TANT7343]
C198  100nF  [RC0402]
DS1  LED-GREEN  [LED-1206]
P3  microUSB  TYPE-AB  [MICRO-USB-AB-RA-SM]
P4  MicroSD-RA-CD-SM  [MicroSD-RA-CD-SM]
P7  uSIM  [SKT-MicroSIM6-SM]
P8  SIM5360 compatible mini PCI express, H=7.5mm  [MINIPCIE-4]
Q19  NDS335N  [SOT23]
R1  10K/1%  [RC0402]
R3  10K/1%  [RC0402]
R106  4.75K/1%  [RC0402]
R107  0R  [RC0402]
R108  10K  [RC0402]
R109  10K  [RC0402]
R119  4.75K/1%  [RC0402]
R120  0R  [RC0402]
R145  1K/1%  [RC0402]
R146  1K/1%  [RC0402]
R147  1K/1%  [RC0402]
R155  10K/1%  [RC0402]
R157  10K/1%  [RC0402]
R166  10K/1%  [RC0402]
R167  680R  [RC0402]
R168  0R  [RC0402]
R169  0R  [RC0402]
R234  10K/1%  [RC0402]
R235  0R  [RC0402]
RN3  10K/8P4R  [RESNET8P0805]
U1  TXS0102  [MO-187DA-8]
U2  IP4220CZ6  [SOT23-6L-H1]
U22  IP4220CZ6  [SOT23-6L]
U23  IP4220CZ6  [SOT23-6L]
U24  CP2104  [MO-220VGGD-8]
U27  24C08  [MO-229VCED-2]
sheet 12 WIFI&Bluetooth
C4  100nF  [RC0402]
C6  10uF/10V  [0402]
C7  100nF  [RC0402]
C41  100nF  [RC0402]
C152  100nF  [RC0402]
C153  100nF  [RC0402]
C171  100nF  [RC0402]
R10  0R  [RC0402]
R11  10K  [RC0402]
R12  10K  [RC0402]
R18  10K  [RC0402]
R19  10K  [RC0402]
R20  10K/1%  [RC0402]
R46  10K/1%  [RC0402]
R47  33R  [RC0402]
R61  0R  [RC0402]
R62  100K  [RC0402]
R63  100K  [RC0402]
R170  10K  [RC0402]
R175  10K  [RC0402]
R176  10K  [RC0402]
R179  10K  [RC0402]
R182  10K  [RC0402]
R237  10K  [RC0402]
R238  10K  [RC0402]
R239  10K  [RC0402]
R240  10K  [RC0402]
U6  AW-CM276NF  [LGA-96-1216-AW]  (sections A,B)
U12  EM7604  [SOT23-6L]
X1  32.768KHz  [XTAL3_2x1_5]
sheet 13 Power
BH1  BATT_HOLDER_1632  [BattH16mm-SM]
BT2  BATT 1632
C8  2.2nF  [RC0402]
C9  2.2nF  [RC0402]
C14  100nF  [RC0402]
C17  10uF/63V  [C1210H2_5]
C20  10uF/63V  [C1210H2_5]
C21  22uF,6.3v  [RC0603]
C22  22uF,6.3v  [RC0603]
C26  100nF  [RC0402]
C32  22uF,6.3v  [RC0603]
C33  22uF,6.3v  [RC0603]
C34  22uF,6.3v  [RC0603]
C44  10uF/63V  [C1210H2_5]
C45  10uF/63V  [C1210H2_5]
C46  22uF,6.3v  [RC0603]
C49  2.2nF  [RC0402]
C50  2.2nF  [RC0402]
C54  100nF  [RC0402]
C55  2.2nF  [RC0402]
C56  2.2nF  [RC0402]
C59  10uF/63V  [C1210H2_5]
C60  2.2nF  [RC0402]
C61  2.2nF  [RC0402]
C66  10uF/63V  [C1210H2_5]
C67  22uF,6.3v  [RC0603]
C68  22uF,6.3v  [RC0603]
C73  10uF/63V  [C1210H2_5]
C74  10uF/63V  [C1210H2_5]
C79  22uF,6.3v  [RC0603]
C80  22uF,6.3v  [RC0603]
C85  100nF  [RC0402]
C96  100nF  [RC0402]
C186  220nF/100V  [RC0603]
DS3  LED-GREEN  [LED-1206]
E2  HDR1X2  [1X2THHDR]
E5  HDR1X2  [1X2THHDR]
L3  6.8uH_3.5A  [IND6x5_5x3]
L4  6.8uH_2.4A  [IND6x5_5x3]
L5  6.8uH_3.5A  [IND6x5_5x3]
L6  6.8uH_3.5A  [IND6x5_5x3]
Q4  NTZD3154NT  [SOT-563-6]  (sections A,B)
Q10  0.5A,20V,Vgs max 6V  [SOT-563-6]
R4  28.7K  [RC0402]
R5  100K  [RC0402]
R6  1K/1%  [RC0402]
R7  4.75k  [RC0402]
R14  100K  [RC0402]
R41  100K  [RC0402]
R42  0.020R,1%  [R1206]
R80  28.7K  [RC0402]
R81  100K  [RC0402]
R82  100K  [RC0402]
R83  1K/1%  [RC0402]
R84  4.75k  [RC0402]
R88  28.7K  [RC0402]
R89  100K  [RC0402]
R90  680R  [RC0402]
R92  100K  [RC0402]
R93  28.7K  [RC0402]
R100  1K/1%  [RC0402]
R101  4.75k  [RC0402]
R102  100K  [RC0402]
R103  1.5K/1%  [RC0402]
R180  56.2K  [RC0402]
R181  17.8K  [RC0402]
R187  64.9K  [RC0402]
R196  17.8K  [RC0402]
R197  0R  [RC0402]
R208  10K/1%  [RC0402]
R209  10K/1%  [RC0402]
R210  22.1k  [RC0402]
R211  17.8K  [RC0402]
R212  12.4K  [RC0402]
R213  64.9K  [RC0402]
U3  RT7272B  [PSOP-8-2X2]
U13  RT7272B  [PSOP-8-2X2]
U14  RT7272B  [PSOP-8-2X2]
U15  RT7272B  [PSOP-8-2X2]
U26  SN74LVC1G17
sheet 14 Mechanical
C25  100nF  [RC0402]
C29  100nF  [RC0402]
C30  100nF  [RC0402]
C31  100nF  [RC0402]
C42  100nF  [RC0402]
C43  100nF  [RC0402]
C47  100nF  [RC0402]
C48  100nF  [RC0402]
C51  100nF  [RC0402]
C52  100nF  [RC0402]
C53  100nF  [RC0402]
C57  100nF  [RC0402]
C58  100nF  [RC0402]
C63  100nF  [RC0402]
C64  100nF  [RC0402]
C65  100nF  [RC0402]
C71  100nF  [RC0402]
C72  100nF  [RC0402]
C78  100nF  [RC0402]
JP1  Jumper, black, 100mil
JP2  Jumper, black, 100mil
JP3  Jumper, black, 100mil
JP4  Jumper, black, 100mil
JP5  Jumper, black, 100mil
JP6  Jumper, black, 100mil
JP7  Jumper, black, 100mil
SP1  TH Spacer, Round, M2 Threaded  [MINIPCIE-4-Spacer]
SP2  TH Spacer, Round, M2 Threaded  [MINIPCIE-4-Spacer]
SPACER1  Spacer, (Standoff), Hex, 4x4 (4.5mm body length), M2, Male/Female  [NONE]
SPACER2  Spacer, (Standoff), Hex, 4x4 (4.5mm body length), M2, Male/Female  [NONE]

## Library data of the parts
C92 C189 = CAP_NP: CLABCONF0: =SBC-MCM93; P/N: 151D15000S
C93 C190 = CAP_NP: CLABCONF0: =SBC-MCM93; P/N: 151C10500S
C94 = 10pF,50V,NPO,_5%,_0402_1: CLABCONF0: DNP
C95 = 10pF,50V,NPO,_5%,_0402: CLABCONF0: DNP
C99 C101 C102 = CAP_NP: CLABCONF0: =SBC-MCM93; P/N: 151B22500S
C41 C100 C130 C141 = 100nF,_10V,_X7R,_10%,_0402_1: CLABCONF0: =SBC-MCM93
C36 C103 = 15pF,_50V,_NPO,_5%,_0402: CLABCONF0: =SBC-MCM93; P/N: 151B47500S
C104 C165 = 15pF,_50V,_NPO,_5%,_0402_1: CLABCONF0: =SBC-MCM93; P/N: 151B47500S
C105 C198 = 100nF,_10V,_X7R,_10%,_0402_2: CLABCONF0: =SBC-MCM93
C111 C170 = 15pF,_50V,_NPO,_5%,_0402_7: CLABCONF0: =SBC-MCM93; P/N: 151B47500S
C112 C143 = 100nF,_10V,_X7R,_10%,_0402: CLABCONF0: =SBC-MCM93
C113 C183 = 15pF,_50V,_NPO,_5%,_0402_2: CLABCONF0: =SBC-MCM93; P/N: 151B47500S
C114 C147 = 100nF,_10V,_X7R,_10%,_0402_3: CLABCONF0: =SBC-MCM93
C116 = 15pF,_50V,_NPO,_5%,_0402_3: CLABCONF0: =SBC-MCM93; P/N: 151B47500S
C117 = 15pF,_50V,_NPO,_5%,_0402_4: CLABCONF0: =SBC-MCM93; P/N: 151B47500S
C118 = 15pF,_50V,_NPO,_5%,_0402_6: CLABCONF0: =SBC-MCM93; P/N: 151B47500S
C119 C177 = 15pF,_50V,_NPO,_5%,_0402_5: CLABCONF0: =SBC-MCM93; P/N: 151B47500S
C120 = 15pF,_50V,_NPO,_5%,_0402_8: CLABCONF0: =SBC-MCM93; P/N: 151B47500S
C127 = CAP_NP: CLABCONF0: =SBC-MCM93; P/N: 151C22620S
C194 = 220pF,50V,NPO,0603_1: CLABCONF0: =SBC-MCM93
C199 = 220pF,50V,NPO,0603: CLABCONF0: =SBC-MCM93
J5 J6 = Audio_JACK,_STEREO+AUX+SW_3.5mm: CLABCONF0: =SBC-MCM93
L7 L17 L18 = Ferrit_330R-100Mhz,1.2A: CLABCONF0: =SBC-MCM93; P/N: 147D12102S
L8 L9 = Ferrit_330R-100Mhz,1.2A: CLABCONF0: DNP; P/N: 147D12102S
R104 R110 = RESISTOR: CLABCONF0: =SBC-MCM93; P/N: 161C20R51S
R105 = 10M,5%,0402,1_16W: CLABCONF0: DNP; P/N: 161C56231S
R58 R111 = 0R,_0402_0_3: CLABCONF0: =SBC-MCM93
R27 R112 = 0R,_0402_0_2: CLABCONF0: =SBC-MCM93
R114 = 0R,_0402_0_1: CLABCONF0: DNP
R122 = 0R,_0402_0_4: CLABCONF0: =SBC-MCM93
R53 R123 = 0R,_0402_0: CLABCONF0: =SBC-MCM93
R124 = 10K,1%,0402,1_16W_0_1: CLABCONF0: DNP
R125 = 10K,1%,0402,1_16W_0_4: CLABCONF0: =SBC-MCM93
R135 R214 = 10K,1%,0402,1_16W_0: CLABCONF0: =SBC-MCM93
R215 = 10K,1%,0402,1_16W_0_3: CLABCONF0: =SBC-MCM93
R216 = 0R,_0402_0_5: CLABCONF0: =SBC-MCM93
R62 R217 = 100K,_0402: CLABCONF0: =SBC-MCM93; P/N: 161C10031S
R166 R218 = 10K,1%,0402,1_16W_0_2: CLABCONF0: =SBC-MCM93
TP3-TP5 = TESTPOINT: CLABCONF0: DNP; P/N: 188Z01370S
U16 = WM8962_BGA_49P_A: IC AUDIO CODEC 24BIT DAC 2 CH ADC 1.8V BGA49; 3D_Mechanical_Footprint_File: ftp://fcl.am.freescale.net/ALLEGRO/step/BGA49_0P5_3P62X4.STEP; AGILE_PN: 315-80353; CAD_APPROVED: Yes; CLABCONF0: =SBC-MCM93; HEIGHT: 0.75MM; MFG_NAME01: WOLFSON MICROELECTRONICS; P/N: 117A10070S; ROHS: Yes; VOLTAGE: 1.8V
X4 = XTAL,24.000Mhz,100ppm,Ind,3x5mm: CLABCONF0: DNP; P/N: 141B24605I
C129 = 1uF,X5R,6.3V,0402: CLABCONF0: =SBC-MCM93; P/N: 151D10510S
C131 = 10uF,6.3V,0603,20%X5R_1: CLABCONF0: =SBC-MCM93
C133 = 100nF,_10V,_X7R,_10%,_0402: CLABCONF0: =SBC-MCM93; P/N: 151C22400S
C206 = 10uF,6.3V,0603,20%X5R: CLABCONF0: =SBC-MCM93
C142 C146 C148 C151 C208 C212 = 1uF,X5R,6.3V,0402: CLABCONF0: =SBC-MCM93
D2 = BAT54WS_0: CLABCONF0: =SBC-MCM93
L10 = INC_DELTA_SI43-100,_10uH: CLABCONF0: =SBC-MCM93; CLABCONF1: <null>
L14 L15 L19-L21 = ESD_CHOKE_DIFFx2_10: CLABCONF0: =SBC-MCM93; P/N: 142D11801S
P13 = HDR_2x7_100MIL_RA_TH_SHRD_0: CLABCONF0: =SBC-MCM93; P/N: 190C00801S
P14 = HDR_2x12_100MIL_0: CLABCONF0: =SBC-MCM93; P/N: 190C02000S
R126 = 0R,_1206: CLABCONF0: =SBC-MCM93
R148 = 2.2R,5%,0402,1_16W_2: CLABCONF0: =SBC-MCM93; P/N: 161C00005S
R149 = 2.2R,5%,0402,1_16W: CLABCONF0: DNP; P/N: 161C06R25S
R150 = 2.2R,5%,0402,1_16W_1: CLABCONF0: =SBC-MCM93; P/N: 161C0R751S
R56 R232 = 0R,_0402: CLABCONF0: =SBC-MCM93
U19 = TPS61165DBVT: CLABCONF0: =SBC-MCM93; P/N: 123C15100S
U2 U22 U23 U28 = IP4220CZ6_0: CLABCONF0: =SBC-MCM93
C23 C24 C27 C28 = 27pF,_50V,_X7R,_10%,_0402: CLABCONF0: =SBC-MCM93; P/N: 151D18000S
C35 = 15pF,_50V,_NPO,_5%,_0402_22: CLABCONF0: =SBC-MCM93; P/N: 151B10400S
C37 = 15pF,_50V,_NPO,_5%,_0402_11: CLABCONF0: =SBC-MCM93; P/N: 151B10400S
C38 = 15pF,_50V,_NPO,_5%,_0402_10: CLABCONF0: =SBC-MCM93; P/N: 151B47500S
C161 = 15pF,_50V,_NPO,_5%,_0402_14: CLABCONF0: =SBC-MCM93; P/N: 151B10400S
C162 = 15pF,_50V,_NPO,_5%,_0402_18: CLABCONF0: =SBC-MCM93; P/N: 151B10400S
C163 = 15pF,_50V,_NPO,_5%,_0402_25: CLABCONF0: =SBC-MCM93; P/N: 151B47500S
C164 = 15pF,_50V,_NPO,_5%,_0402_19: CLABCONF0: =SBC-MCM93; P/N: 151B10400S
C166 = 15pF,_50V,_NPO,_5%,_0402_17: CLABCONF0: =SBC-MCM93; P/N: 151B10400S
C167 = 15pF,_50V,_NPO,_5%,_0402_27: CLABCONF0: =SBC-MCM93; P/N: 151B10400S
C168 = 15pF,_50V,_NPO,_5%,_0402_9: CLABCONF0: =SBC-MCM93; P/N: 151B47500S
C169 = 15pF,_50V,_NPO,_5%,_0402_8: CLABCONF0: =SBC-MCM93; P/N: 151B10400S
C172 = 15pF,_50V,_NPO,_5%,_0402_6: CLABCONF0: =SBC-MCM93; P/N: 151B10400S
C173 = 15pF,_50V,_NPO,_5%,_0402_15: CLABCONF0: =SBC-MCM93; P/N: 151B47500S
C174 = 15pF,_50V,_NPO,_5%,_0402_16: CLABCONF0: =SBC-MCM93; P/N: 151B47500S
C175 = 15pF,_50V,_NPO,_5%,_0402_13: CLABCONF0: =SBC-MCM93; P/N: 151B10400S
C176 = 15pF,_50V,_NPO,_5%,_0402_23: CLABCONF0: =SBC-MCM93; P/N: 151B47500S
C178 = 15pF,_50V,_NPO,_5%,_0402_3: CLABCONF0: =SBC-MCM93; P/N: 151B10400S
C179 = 15pF,_50V,_NPO,_5%,_0402_4: CLABCONF0: =SBC-MCM93; P/N: 151B10400S
C180 = 15pF,_50V,_NPO,_5%,_0402_26: CLABCONF0: =SBC-MCM93; P/N: 151B47500S
C181 = 15pF,_50V,_NPO,_5%,_0402_12: CLABCONF0: =SBC-MCM93; P/N: 151B47500S
C182 = 15pF,_50V,_NPO,_5%,_0402_20: CLABCONF0: =SBC-MCM93; P/N: 151B10400S
C184 = 15pF,_50V,_NPO,_5%,_0402_21: CLABCONF0: =SBC-MCM93; P/N: 151B47500S
C185 = 15pF,_50V,_NPO,_5%,_0402_24: CLABCONF0: =SBC-MCM93; P/N: 151B10400S
FB3 = Ferrite_bead_,_120_Ohm@3A_1: CLABCONF0: =SBC-MCM93; P/N: 147D22101S
FB4 = Ferrite_bead_,_120_Ohm@3A: CLABCONF0: =SBC-MCM93; P/N: 147D22101S
R28 R238 = 1M_,5%,_0402_3: CLABCONF0: =SBC-MCM93; P/N: 161C10021S
R29 = 1M_,5%,_0402_2: CLABCONF0: =SBC-MCM93; P/N: 161C24911S
R30 = 0R,_0402_0_1: CLABCONF0: =SBC-MCM93
R18 R31 = 1M_,5%,_0402_5: CLABCONF0: =SBC-MCM93; P/N: 161C10021S
R32 = 1M_,5%,_0402_1: CLABCONF0: =SBC-MCM93; P/N: 161C24911S
R43 = 4.75K,1%,0402,1_16W_11: CLABCONF0: =SBC-MCM93
R44 = 4.75K,1%,0402,1_16W_4: CLABCONF0: =SBC-MCM93
R48 = 0R,_0402_1_2: CLABCONF0: =SBC-MCM93
R50 = 33R,5%,0402,1_16W_0: CLABCONF0: =SBC-MCM93; P/N: 161C33R05S
R51 R195 = 0R,_0402_1: CLABCONF0: =SBC-MCM93
R52 = 1M_,5%,_0402: CLABCONF0: =SBC-MCM93; P/N: 161C47511S
R54 = 4.75K,1%,0402,1_16W_18: CLABCONF0: =SBC-MCM93
R55 = 33R,5%,0402,1_16W_0_1: CLABCONF0: =SBC-MCM93; P/N: 161C33R05S
R57 = 1M_,5%,_0402_4: CLABCONF0: =SBC-MCM93; P/N: 161C47511S
R59 = 4.75K,1%,0402,1_16W_12: CLABCONF0: =SBC-MCM93
R65 = 4.75K,1%,0402,1_16W_9: CLABCONF0: =SBC-MCM93
R66 = 4.75K,1%,0402,1_16W_21: CLABCONF0: =SBC-MCM93
R67 = 4.75K,1%,0402,1_16W_30: CLABCONF0: DNP
R68 = 4.75K,1%,0402,1_16W_17: CLABCONF0: DNP
R69 = 4.75K,1%,0402,1_16W_31: CLABCONF0: DNP
R70 = 4.75K,1%,0402,1_16W_27: CLABCONF0: =SBC-MCM93
R71 = 4.75K,1%,0402,1_16W_25: CLABCONF0: DNP
R72 = 4.75K,1%,0402,1_16W_19: CLABCONF0: =SBC-MCM93
R73 = 4.75K,1%,0402,1_16W: CLABCONF0: DNP
R74 = 4.75K,1%,0402,1_16W_7: CLABCONF0: DNP
R75 = 4.75K,1%,0402,1_16W_15: CLABCONF0: DNP
R76 = 4.75K,1%,0402,1_16W_32: CLABCONF0: =SBC-MCM93
R178 = 0R,_0402_1_1: CLABCONF0: =SBC-MCM93
R183 = 4.75K,1%,0402,1_16W_24: CLABCONF0: =SBC-MCM93
R184 = 4.75K,1%,0402,1_16W_10: CLABCONF0: DNP
R185 = 4.75K,1%,0402,1_16W_5: CLABCONF0: =SBC-MCM93
R186 = 4.75K,1%,0402,1_16W_8: CLABCONF0: DNP
R190 = 4.75K,1%,0402,1_16W_23: CLABCONF0: DNP
R103 R191 = 1.5K_1%,_0402: CLABCONF0: =SBC-MCM93
R192 = 0R,_0402_1_3: CLABCONF0: =SBC-MCM93
R193 = 4.75K,1%,0402,1_16W_16: CLABCONF0: DNP
R194 = 1.5K_1%,_0402_1: CLABCONF0: =SBC-MCM93
R198 = 4.75K,1%,0402,1_16W_2: CLABCONF0: =SBC-MCM93
R199 = 4.75K,1%,0402,1_16W_28: CLABCONF0: =SBC-MCM93
R200 = 4.75K,1%,0402,1_16W_1: CLABCONF0: =SBC-MCM93
R201 = 4.75K,1%,0402,1_16W_14: CLABCONF0: DNP
R202 = 4.75K,1%,0402,1_16W_13: CLABCONF0: =SBC-MCM93
R203 = 4.75K,1%,0402,1_16W_26: CLABCONF0: =SBC-MCM93
R204 = 4.75K,1%,0402,1_16W_3: CLABCONF0: =SBC-MCM93
R205 = 4.75K,1%,0402,1_16W_20: CLABCONF0: =SBC-MCM93
R206 = 4.75K,1%,0402,1_16W_29: CLABCONF0: DNP
R207 = 4.75K,1%,0402,1_16W_22: CLABCONF0: DNP
R236 = 4.75K,1%,0402,1_16W_6: CLABCONF0: DNP
U9 U10 = RTL8211FDI-40P_A_0: IC XCVR ETH INTEGRATED 10/100/1000MBPS RGMII 3.3V/2.5V/1.8V QFN40; 3D_Mechanical_Footprint_File: http://fcl.am.freescale.net/ALLEGRO/step/qfn40_0p4_5x5mm.STEP; AGILE_PN: TMP-CIP-10596; CAD_APPROVED: Yes; CLABCONF0: =SBC-MCM93; HEIGHT: 0.9MM; MFG_NAME01: REALTEK SEMICONDUCTOR; P/N: 116A00640S; PRE_APN: 312-83499; Package Size: QFN40; ROHS: Yes; Temp Range: -40  °C  +85 °C
X2 X3 = XTAL,_25.000Mhz,_3x5mm: CLABCONF0: =SBC-MCM93; P/N: 141B25603I
C1 C3 = 100nF,_10V,_X7R,_10%,_0402_0: CLABCONF0: =SBC-MCM93
C2 = 4.7uF,_6.3V,_X5R,_20%,_0603: CLABCONF0: DNP; P/N: 151B10610S
C91 = 100nF,_10V,_X7R,_10%,_0402_6: CLABCONF0: =SBC-MCM93
C14 C26 C54 C85 C107 C109 C110 C137 C138 = 100nF,_10V,_X7R,_10%,_0402_0: CLABCONF0: =SBC-MCM93; Group: LAN2
C108 = 10uF,6.3V,0603,20%X5R: CLABCONF0: =SBC-MCM93; P/N: 151B10610S
C144 = 100nF,_10V,_X7R,_10%,_0402_4: CLABCONF0: =SBC-MCM93
C145 = 100nF,_10V,_X7R,_10%,_0402_5: CLABCONF0: =SBC-MCM93
C193 = CAPACITOR_POL: CLABCONF0: =SBC-MCM93; P/N: 154A687D0S
DS1 DS3 = LED-GREEN_1206_2: CLABCONF0: =SBC-MCM93
P3 = Conn.,_Micro-USB,_B-Type: CLABCONF0: =SBC-MCM93; P/N: 180K00501S
P4 = microSD_push-pull: CLABCONF0: =SBC-MCM93; P/N: 182K01300S
P7 = uSIM_SOCKET_0: CLABCONF0: =SBC-MCM93
P8 = Conn.,_Mini-PCIe,_for_SIM5360: CLABCONF0: =SBC-MCM93; P/N: 182K05203S
Q19 = N-MOSFET,NDS335N,100mOhm@2.5V: CLABCONF0: =SBC-MCM93
R1 = 10K,1%,0402,1_16W_3: CLABCONF0: =SBC-MCM93
R3 R46 R209 = 10K,1%,0402,1_16W: CLABCONF0: =SBC-MCM93
R106 = 4_0.75K,1%,0402,1_16W_1: CLABCONF0: =SBC-MCM93
R107 = 0R,_0402_0_3: CLABCONF0: =SBC-MCM93; P/N: 161C00005S
R108 = 10K,1%,0402,1_16W_0_1: CLABCONF0: DNP; Group: Always
R109 = 10K,1%,0402,1_16W_0: CLABCONF0: DNP; Group: Always
R119 = 4_0.75K,1%,0402,1_16W: CLABCONF0: =SBC-MCM93
R61 R120 = 0R,_0402_0_1: CLABCONF0: =SBC-MCM93; P/N: 161C00005S
R145 = 1K,1%,0402,1_16W_1: CLABCONF0: DNP; Group: CAN
R146 = 1K,1%,0402,1_16W: CLABCONF0: DNP; Group: CAN
R100 R147 = 1K,1%,0402,1_16W_2: CLABCONF0: =SBC-MCM93; Group: CAN
R155 = 10K,1%,0402,1_16W_2: CLABCONF0: =SBC-MCM93
R157 R208 = 10K,1%,0402,1_16W_1: CLABCONF0: =SBC-MCM93
R90 R167 = 47K,_0402: CLABCONF0: =SBC-MCM93; P/N: 161C68001S
R168 = 0R,_0402_0_4: CLABCONF0: DNP; P/N: 161C00005S
R10 R169 = 0R,_0402_0: CLABCONF0: =SBC-MCM93; P/N: 161C00005S
R234 = 10K,1%,0402,1_16W_4: CLABCONF0: =SBC-MCM93
R235 = 0R,_0402_0_2: CLABCONF0: DNP; P/N: 161C00005S
RN3 = RN,10K,8P4R@0805: CLABCONF0: =SBC-MCM93
U1 = TXS0102_0: CLABCONF0: =SBC-MCM93; P/N: 116A01020S
U24 = CP2104_0: CLABCONF0: =SBC-MCM93; P/N: 116A00140S
U27 = 24C02,_serial_EE,_2KB,_I2C: CLABCONF0: =SBC-MCM93; P/N: 111S31000S
C4 C25 = 100nF,_10V,_X7R,_10%,_0402_4: CLABCONF0: =SBC-MCM93; P/N: 151B10400S
C6 = 10uF_10V_20%_0402: CLABCONF0: =SBC-MCM93
C7 C63 = 100nF,_10V,_X7R,_10%,_0402_3: CLABCONF0: =SBC-MCM93; P/N: 151B10400S
C78 C152 = 100nF,_10V,_X7R,_10%,_0402: CLABCONF0: =SBC-MCM93; P/N: 151B10400S
C48 C153 = 100nF,_10V,_X7R,_10%,_0402_5: CLABCONF0: =SBC-MCM93; P/N: 151B10400S
C43 C171 = 100nF,_10V,_X7R,_10%,_0402_2: CLABCONF0: =SBC-MCM93; P/N: 151B10400S
R11 = 1M_,5%,_0402: CLABCONF0: =SBC-MCM93; P/N: 161C10021S
R12 = 1M_,5%,_0402_10: CLABCONF0: =SBC-MCM93; P/N: 161C10021S
R19 = 1M_,5%,_0402_9: CLABCONF0: =SBC-MCM93; P/N: 161C10021S
R20 = 10K,1%,0402,1_16W_0: CLABCONF0: DNP; P/N: 161C10021S
R47 = 33R,5%,0402,1_16W: CLABCONF0: =SBC-MCM93
R63 = 100K,_0402_1: CLABCONF0: =SBC-MCM93; P/N: 161C10031S
R170 = 1M_,5%,_0402_12: CLABCONF0: =SBC-MCM93; P/N: 161C10021S
R175 = 1M_,5%,_0402_7: CLABCONF0: =SBC-MCM93; P/N: 161C10021S
R176 = 1M_,5%,_0402_1: CLABCONF0: =SBC-MCM93; P/N: 161C10021S
R179 = 1M_,5%,_0402_11: CLABCONF0: =SBC-MCM93; P/N: 161C10021S
R182 = 1M_,5%,_0402_8: CLABCONF0: =SBC-MCM93; P/N: 161C10021S
R237 = 1M_,5%,_0402_2: CLABCONF0: =SBC-MCM93; P/N: 161C10021S
R239 = 1M_,5%,_0402_4: CLABCONF0: =SBC-MCM93; P/N: 161C10021S
R240 = 1M_,5%,_0402_6: CLABCONF0: =SBC-MCM93; P/N: 161C10021S
U6 = AW-CM276NF: CLABCONF0: =SBC-MCM93; P/N: 116B00550S; Color: Default; Location X-Coordinate: 0; Location Y-Coordinate: 0; Primitive: DEFAULT
U12 = OSC.,_26.000MHz,100PPM,_1_1.8V: CLABCONF0: =SBC-MCM93; P/N: 105I76040S
X1 = XTAL,_32.768KHZ,_20PPM,_4x1.5mm: CLABCONF0: =SBC-MCM93; P/N: 141B32301I
BH1 = BATT_HOLDER_1: CLABCONF0: =SBC-MCM93; P/N: 190Z00300S
BT2 = BATT_2032: CLABCONF0: =SBC-MCM93; P/N: 210C30006
C8 = 2.2nF,_50V,_X7R,_10%,_0402_5: CLABCONF0: DNP
C9 = 2.2nF,_50V,_X7R,_10%,_0402: CLABCONF0: =SBC-MCM93
C17 C20 C59 C66 C73 C74 = 22uF_25V: CLABCONF0: =SBC-MCM93; P/N: 151E10680S
C21 = 100nF,_10V,_X7R,_10%,_0402_1: CLABCONF0: =SBC-MCM93; P/N: 151B22610S
C22 = 100nF,_10V,_X7R,_10%,_0402_3: CLABCONF0: =SBC-MCM93; P/N: 151B22610S
C32 = 100nF,_10V,_X7R,_10%,_0402_7: CLABCONF0: =SBC-MCM93; P/N: 151B22610S
C33 = 100nF,_10V,_X7R,_10%,_0402_11: CLABCONF0: =SBC-MCM93; P/N: 151B22610S
C34 = 100nF,_10V,_X7R,_10%,_0402_2: CLABCONF0: =SBC-MCM93; P/N: 151B22610S
C44 C45 = 22uF_25V: CLABCONF0: =SBC-MCM93; P/N: 151D10630S
C46 = 100nF,_10V,_X7R,_10%,_0402_9: CLABCONF0: =SBC-MCM93; P/N: 151B22610S
C49 = 2.2nF,_50V,_X7R,_10%,_0402_7: CLABCONF0: DNP
C50 = 2.2nF,_50V,_X7R,_10%,_0402_1: CLABCONF0: =SBC-MCM93
C55 = 2.2nF,_50V,_X7R,_10%,_0402_6: CLABCONF0: DNP
C56 = 2.2nF,_50V,_X7R,_10%,_0402_2: CLABCONF0: =SBC-MCM93
C60 = 2.2nF,_50V,_X7R,_10%,_0402_3: CLABCONF0: =SBC-MCM93
C61 = 2.2nF,_50V,_X7R,_10%,_0402_4: CLABCONF0: DNP
C67 = 100nF,_10V,_X7R,_10%,_0402_4: CLABCONF0: =SBC-MCM93; P/N: 151B22610S
C68 = 100nF,_10V,_X7R,_10%,_0402_10: CLABCONF0: =SBC-MCM93; P/N: 151B22610S
C79 = 100nF,_10V,_X7R,_10%,_0402: CLABCONF0: =SBC-MCM93; P/N: 151B22610S
C80 = 100nF,_10V,_X7R,_10%,_0402_8: CLABCONF0: =SBC-MCM93; P/N: 151B22610S
C96 = 100nF,_10V,_X7R,_10%,_0402_6: CLABCONF0: DNP; P/N: 151B10400S
C186 = 100nF,_10V,_X7R,_10%,_0402_5: CLABCONF0: =SBC-MCM93; P/N: 151E22410S
E2 = HDR_1x2_100MIL_TH_JUMPER_1: CLABCONF0: =SBC-MCM93
E5 = HDR_1x2_100MIL_TH_JUMPER: CLABCONF0: =SBC-MCM93
L3 L5 L6 = IND_6.8uH_3.5A: CLABCONF0: =SBC-MCM93; P/N: 147A6R802S
L4 = IND_6.8uH_3.5A: CLABCONF0: =SBC-MCM93; P/N: 147A6R804S
Q4 = N-MOSFET_Dual: CLABCONF0: =SBC-MCM93; P/N: 131D31540S
Q10 = DUAL_N-MOSFET,_0.5A_20V: CLABCONF0: =SBC-MCM93
R4 R80 R88 R93 = 40.2k_1%: CLABCONF0: =SBC-MCM93; P/N: 161C28721S
R5 R82 R102 = 100K,_0402_0: CLABCONF0: DNP
R6 = 1K,1%,0402,1_16W: CLABCONF0: =SBC-MCM93; Group: CAN
R7 R84 R101 = 100K,_0402_0: CLABCONF0: DNP; P/N: 161C47511S
R14 R41 R81 R89 R92 = 100K,_0402_0: CLABCONF0: =SBC-MCM93
R42 = RESISTOR: CLABCONF0: =SBC-MCM93; P/N: 161G02011S; Part Name: Res., 0.020R, 1%, 1206, 1/2W (Current sense)
R83 = 1K,1%,0402,1_16W_1: CLABCONF0: =SBC-MCM93; Group: CAN
R180 = 10.5K_1%,0402: CLABCONF0: =SBC-MCM93; P/N: 161C56221S
R181 R196 R211 = 2.37K_1%,_0402: CLABCONF0: =SBC-MCM93; P/N: 161C17821S
R187 R213 = 10.5K_1%,0402: CLABCONF0: =SBC-MCM93; P/N: 161C64921S
R197 = 0R,_0402: CLABCONF0: DNP
R210 = RESISTOR: CLABCONF0: =SBC-MCM93; P/N: 161C22121S
R212 = 2.37K_1%,_0402: CLABCONF0: =SBC-MCM93; P/N: 161C12421S
U3 U13-U15 = RT7272B,Converter,3A,36V: CLABCONF0: =SBC-MCM93; P/N: 123V30000S
U26 = SN74LVC1G17: CLABCONF0: =SBC-MCM93; P/N: 106D90000S
C29 = 100nF,_10V,_X7R,_10%,_0402_7: CLABCONF0: =SBC-MCM93; P/N: 151B10400S
C30 = 100nF,_10V,_X7R,_10%,_0402_6: CLABCONF0: =SBC-MCM93; P/N: 151B10400S
C31 = 100nF,_10V,_X7R,_10%,_0402_17: CLABCONF0: =SBC-MCM93; P/N: 151B10400S
C42 = 100nF,_10V,_X7R,_10%,_0402_8: CLABCONF0: =SBC-MCM93; P/N: 151B10400S
C47 = 100nF,_10V,_X7R,_10%,_0402_14: CLABCONF0: =SBC-MCM93; P/N: 151B10400S
C51 = 100nF,_10V,_X7R,_10%,_0402_16: CLABCONF0: =SBC-MCM93; P/N: 151B10400S
C52 = 100nF,_10V,_X7R,_10%,_0402_15: CLABCONF0: =SBC-MCM93; P/N: 151B10400S
C53 = 100nF,_10V,_X7R,_10%,_0402_11: CLABCONF0: =SBC-MCM93; P/N: 151B10400S
C57 = 100nF,_10V,_X7R,_10%,_0402_1: CLABCONF0: =SBC-MCM93; P/N: 151B10400S
C58 = 100nF,_10V,_X7R,_10%,_0402_13: CLABCONF0: =SBC-MCM93; P/N: 151B10400S
C64 = 100nF,_10V,_X7R,_10%,_0402_12: CLABCONF0: =SBC-MCM93; P/N: 151B10400S
C65 = 100nF,_10V,_X7R,_10%,_0402_18: CLABCONF0: =SBC-MCM93; P/N: 151B10400S
C71 = 100nF,_10V,_X7R,_10%,_0402_10: CLABCONF0: =SBC-MCM93; P/N: 151B10400S
C72 = 100nF,_10V,_X7R,_10%,_0402_9: CLABCONF0: =SBC-MCM93; P/N: 151B10400S
JP1-JP7 = Jumper,_black,_100mil: CLABCONF0: =SBC-MCM93
SP1 SP2 = SMT_SPACER_M2x3_2: CLABCONF0: =SBC-MCM93; P/N: 383B52531S
SPACER1 SPACER2 = Hexagonal_Standoff_0: CLABCONF0: =SBC-MCM93; P/N: 206C10160

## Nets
1V8_L: C104.2 C105.1 C113.2 C120.2 L7.1 U16.C6(CPVDD) U16.D6(AVDD) U16.G2(DCVDD) U16.G4(PLLVDD)
3V3_WLAN: C4.2 C6.2 C7.2 C41.1 C153.2 R10.1 R46.1 U6.4(VCC1) U6.5(VCC2) U6.72(VCC3) U12.5(VDD)
5V0_L: C117.2 C118.2 C127.1 L8.1 L9.1 U16.A2(SPKVDD1) U16.C2(SPKVDD2)
GND: BH1.2N(-) C1.2 C2.2 C3.1 C4.1 C6.1 C7.1 C8.2 C17.2 C20.2 C21.1 C22.1 C23.1 C24.1 C25.2 C27.1 C28.1 C29.2 C30.2 C31.2 C32.1 C33.1 C34.1 C35.1 C36.1 C37.1 C38.1 C41.2 C42.2 C43.2 C44.2 C45.2 C46.1 C47.2 C48.2 C49.2 C51.2 C52.2 C53.2 C55.2 C57.2 C58.2 C59.2 C61.2 C63.2 C64.2 C65.2 C66.2 C67.1 C68.1 C71.2 C72.2 C73.2 C74.2 C78.2 C79.1 C80.1 C91.1 C92.1 C94.1 C95.1 C96.2 C99.2 C101.2 C103.1 C104.1 C105.2 C107.2 C108.2 C109.2 C110.2 C111.2 C113.1 C114.2 C116.1 C117.1 C118.1 C119.1 C120.1 C127.2 C129.2 C130.2 C131.2 C133.2 C137.2 C138.2 C141.2 C142.2 C143.2 C144.2 C145.2 C146.2 C147.2 C148.2 C151.2 C152.1 C153.1 C161.1 C162.1 C163.1 C164.1 C165.1 C166.1 C167.1 C168.1 C169.1 C170.1 C171.1 C172.1 C173.1 C174.1 C175.1 C176.1 C177.1 C178.1 C179.1 C180.1 C181.1 C182.1 C183.1 C184.1 C185.1 C186.2 C189.1 C193.2 C194.1 C198.1 C199.1 C208.1 C212.1 DS1.CATHODE DS3.CATHODE J5.1(COM) J6.1(COM) L14.5(GND) L14.6(GND) L15.5(GND) L15.6(GND) L19.5(GND) L19.6(GND) L20.5(GND) L20.6(GND) L21.5(GND) L21.6(GND) P3.5(GND) P3.6(SHIELD1) P3.7(SHIELD2) P3.8(SHIELD3) P3.9(SHIELD4) P4.G1 P4.G2 P4.G3 P4.G4 P4.P6(VSS) P4.SH1 P4.SH2 P7.5(GND) P7.9(M9) P7.10(M10) P7.11(M11) P7.12(M12) P8.4(GND) P8.9(GND) P8.15(GND) P8.18(GND) P8.21(GND) P8.26(GND) P8.27(GND) P8.29(GND) P8.34(GND) P8.35(GND) P8.37(GND) P8.40(GND) P8.43(GND) P8.50(GND) P13.8 P14.1 P14.2 P14.7 P14.8 P14.13 P14.14 Q4.4(S) Q10.1(S1) Q10.4(S2) Q19.2(S) R4.2 R11.2 R14.2 R18.2 R20.1 R29.1 R32.1 R65.2 R66.2 R67.2 R68.2 R69.2 R70.2 R71.1 R72.2 R73.2 R74.2 R75.2 R76.2 R80.2 R81.2 R88.2 R89.2 R92.2 R93.2 R104.2 R110.2 R111.2 R148.2 R155.1 R175.2 R181.2 R183.2 R184.2 R185.2 R186.2 R190.2 R193.2 R196.2 R211.2 R212.2 R214.2 R215.2 R217.2 R234.1 RN3.1(RA1) RN3.2(RB1) RN3.3(RC1) RN3.4(RD1) SP1.1 SP2.1 U1.2(GND) U2.2(GND) U3.4(GND) U3.9(PAD) U6.6(GND1) U6.17(GND2) U6.20(GND3) U6.23(GND4) U6.26(GND5) U6.32(GND6) U6.35(GND7) U6.38(GND8) U6.41(GND9) U6.62(GND10) U6.68(GND11) U6.71(GND12) U6.74(GND13) U6.75(GND14) U6.76(GND15) U6.77(GND16) U6.78(GND17) U6.79(GND18) U6.80(GND19) U6.81(GND20) U6.82(GND21) U6.83(GND22) U6.84(GND23) U6.85(GND24) U6.86(GND25) U6.87(GND26) U6.88(GND27) U6.89(GND28) U6.90(GND29) U6.91(GND30) U6.92(GND31) U6.93(GND32) U6.94(GND33) U6.95(GND34) U6.96(GND35) U6.G1(GND36) U6.G2(GND37) U6.G3(GND38) U6.G4(GND39) U6.G5(GND40) U6.G6(GND41) U6.G7(GND42) U6.G8(GND43) U6.G9(GND44) U6.G10(GND45) U6.G11(GND46) U6.G12(GND47) U6.G13(GND48) U6.G14(GND49) U6.G15(GND50) U6.G16(GND51) U6.G19(GND54) U6.G20(GND55) U6.G21(GND56) U6.G22(GND57) U6.G23(GND58) U6.G24(GND59) U6.G25(GND60) U6.G26(GND61) U6.G27(GND62) U6.G28(GND63) U6.G29(GND64) U6.G30(GND65) U6.G31(GND66) U6.G32(GND67) U6.G33(GND68) U6.G34(GND69) U6.G35(GND70) U6.G36(GND71) U9.41(GND) U10.41(GND) U12.2(GND) U13.4(GND) U13.9(PAD) U14.4(GND) U14.9(PAD) U15.4(GND) U15.9(PAD) U16.B1(SPKGND1) U16.C1(SPKGND2) U16.C7(CPGND) U16.D7(AGND) U16.F2(CIFMODE) U16.F3(DGND) U16.G5(PLLGND) U19.4(GND) U22.2(GND) U23.2(GND) U24.2(GND) U26.3(GND) U27.4(GND) U28.2(GND) X2.2 X2.4 X3.2 X3.4 X4.2 X4.4 ; also on sheet 1 3 4 5 6 7
V1V8_BOOT: C54.1 U14.2(BOOT)
V1V8_COMP: C49.1 C50.1 U14.6(COMP)
V1V8_COMP_C: C50.2 R80.1
V1V8_EN: R82.1 R83.2 R84.1 U14.3(EN)
V1V8_FB: R210.2 R211.1 U14.5(FB)
V1V8_RLIM: R81.1 U14.7(RLIM)
V1V8_SW: C54.2 L5.1 U14.1(SW)
V3V3_BOOT: C14.1 U3.2(BOOT)
V3V3_COMP: C8.1 C9.1 U3.6(COMP)
V3V3_COMP_C: C9.2 R4.1
V3V3_EN: R5.1 R6.2 R7.1 U3.3(EN)
V3V3_FB: R180.2 R181.1 U3.5(FB)
V3V3_RLIM: R14.1 U3.7(RLIM)
V3V3_SW: C14.2 L3.1 U3.1(SW)
V5_BOOT: C85.1 U15.2(BOOT)
V5_COMP: C60.1 C61.1 U15.6(COMP)
V5_COMP_C: C60.2 R93.1
V5_FB: R212.1 R213.2 U15.5(FB)
V5_RLIM: R92.1 U15.7(RLIM)
V5_SW: C85.2 L6.1 U15.1(SW)
V5V0_EN: R100.2 R101.1 R102.1 U15.3(EN)
VCC_1V8: C67.2 C68.2 C171.2 L5.2 L7.2 R51.2 R56.2 R179.2 R182.2 R210.1 R237.2 R238.2 R239.2 R240.2 U6.44(VIO_SD) ; also on sheet 3 6
VCC_3V3: C1.1 C21.2 C22.2 C51.1 C52.1 C53.1 C57.1 C58.1 C63.1 C64.1 C65.1 C71.1 C72.1 C78.1 C107.1 C108.1 C110.1 C114.1 C116.2 C119.2 C137.1 C152.2 C172.2 C174.2 C179.2 C181.2 C193.1 C198.2 C208.2 C212.2 FB3.2 FB4.2 L3.2 L8.2 P8.2(+3.3V_AUX) P8.39(3.3V_AUX) P8.41(3.3V_AUX) P8.52(+3.3V_AUX) P13.2 P14.20 R3.2 R10.2 R12.1 R19.2 R28.2 R31.2 R43.1 R44.1 R52.1 R54.1 R57.1 R59.1 R62.1 R63.2 R106.1 R108.1 R109.1 R119.1 R124.1 R125.1 R145.2 R146.2 R147.2 R168.1 R170.2 R176.2 R180.1 R218.1 U1.3(VCCA) U6.73(VIO) U9.29(DVDD33) U10.29(DVDD33) U16.A3(MICVDD) U16.G3(DBVDD) U27.8(VCC) U28.5(VBUS) ; also on sheet 1 3 4 5 6 7
VCC_5V0: C79.2 C80.2 L6.2 L9.2 R126.1 R213.1 ; also on sheet 3 5 6
VCC_RTC: E5.1 ; also on sheet 4
VCC_SD: C141.1 C144.1 C145.1 C147.1 C148.1 C151.1 P4.P4(VDD) R166.1 R168.2 R169.1 U22.5(VBUS) U23.5(VBUS)
32KHZ_WLANCLK: R47.2 U6.27(SLP_CLK)
+ETH1_1V0: C35.2 C36.2 R178.2 R195.2 U9.30(LDO_OUT)
+ETH1_DVDD_RG: C182.2 C183.2 R51.1 R194.2 R203.2 R204.1 R205.2 R206.1 R207.2 U9.28(DVDD_RG)
+ETH2_1V0: C37.2 C38.2 R48.2 R192.2 U10.30(LDO_OUT)
+ETH2_DVDD_RG: C175.2 C176.2 R56.1 R191.2 R198.2 R199.1 R200.2 R201.1 R202.2 R236.1 U10.28(DVDD_RG)
AUD_SCL: R123.1 U16.F1(SCLK)
AUD_SDA: R122.1 U16.E2(SDA)
C_VOTN: C101.1 U16.A7(CPVOUTN)
C_VOTP: C99.1 U16.A6(CPVOUTP)
CARRIER_EEPROM_WP: R155.2 U27.7(WP)
CLKOUT2: TP5.1 U16.E4(CLKOUT2/GPIO2)
CLKOUT5: TP3.1 U16.G6(CLKOUT5)
CODEC_INT: R114.2 R125.2 U16.E3(~{CS}/GPIO6)
CON_UART1_RXD: U1.1(B2) U24.21(TXD)
CON_UART1_TXD: U1.8(B1) U24.20(RXD)
CP2104VPP: C2.1 U24.16(VPP)
CPCA: C102.1 U16.B6(CPCA)
CPCB: C102.2 U16.B7(CPCB)
ECSPI4_MOSI/GPIO2_20: R232.2 ; also on sheet 4
ENET1_MDC: U9.13(MDC) ; also on sheet 4
ENET1_MDIO: R194.1 U9.14(MDIO) ; also on sheet 4
ENET1_nRST: R27.1 R28.1 U9.12(~{PHYRST})
ENET1_RD0: R68.1 R204.2 U9.25(RXD0/RXDLY) ; also on sheet 4
ENET1_RD1: R67.1 R205.1 U9.24(RXD1/TXDLY) ; also on sheet 4
ENET1_RD2: R66.1 R206.2 U9.23(RXD2/PLLOFF) ; also on sheet 4
ENET1_RD3: R65.1 R207.1 U9.22(RXD3/PHYAD0) ; also on sheet 4
ENET1_RX_CTL: R69.1 R203.1 U9.26(RXCTL/PHYAD2) ; also on sheet 4
ENET1_RXC: R50.1 R70.1 ; also on sheet 4
ENET1_TD0: U9.18(TXD0) ; also on sheet 4
ENET1_TD1: U9.17(TXD1) ; also on sheet 4
ENET1_TD2: U9.16(TXD2) ; also on sheet 4
ENET1_TD3: U9.15(TXD3) ; also on sheet 4
ENET1_TX_CTL: U9.19(TXCTL) ; also on sheet 4
ENET1_TXC: U9.20(TXC) ; also on sheet 4
ENET2_MDC: U10.13(MDC) ; also on sheet 4
ENET2_MDIO: R191.1 U10.14(MDIO) ; also on sheet 4
ENET2_nRST: R30.1 R31.1 U10.12(~{PHYRST})
ENET2_RD0: R74.1 R199.2 U10.25(RXD0/RXDLY) ; also on sheet 4
ENET2_RD1: R73.1 R200.1 U10.24(RXD1/TXDLY) ; also on sheet 4
ENET2_RD2: R72.1 R201.2 U10.23(RXD2/PLLOFF) ; also on sheet 4
ENET2_RD3: R71.2 R202.1 U10.22(RXD3/PHYAD0) ; also on sheet 4
ENET2_RX_CTL: R75.1 R198.1 U10.26(RXCTL/PHYAD2) ; also on sheet 4
ENET2_RXC: R55.1 R76.1 R236.2 ; also on sheet 4
ENET2_TD0: U10.18(TXD0) ; also on sheet 4
ENET2_TD1: U10.17(TXD1) ; also on sheet 4
ENET2_TD2: U10.16(TXD2) ; also on sheet 4
ENET2_TD3: U10.15(TXD3) ; also on sheet 4
ENET2_TX_CTL: U10.19(TXCTL) ; also on sheet 4
ENET2_TXC: U10.20(TXC) ; also on sheet 4
EPR_A0: R145.1 RN3.8(RA2) U27.1(A0)
EPR_A1: R146.1 RN3.7(RB2) U27.2(A1)
EPR_A2: R147.1 RN3.6(RC2) U27.3(A2)
ETH1_AVDD10: C167.2 C168.2 C169.2 C180.2 R178.1 U9.3(AVDD10_1) U9.8(AVDD10_2) U9.38(AVDD10_3)
ETH1_AVDD33: C166.2 C170.2 FB3.1 U9.11(AVDD33_1) U9.40(AVDD33_2)
ETH1_DVDD10: C184.2 C185.2 R195.1 U9.21(DVDD10)
ETH1_LED0/CFG_EXT: R43.2 R186.1 U9.32(LED0/CFG_EXT) ; also on sheet 1
ETH1_LED1/CFG_LDO0: R185.1 U9.33(LED1/CFG_LDO0)
ETH1_LED2/CFG_LDO1: R54.2 R193.1 U9.34(LED2/CFG_LDO1) ; also on sheet 1
ETH1_MDI0N: U9.2(MDIN0) ; also on sheet 1
ETH1_MDI0P: U9.1(MDIP0) ; also on sheet 1
ETH1_MDI1N: U9.5(MDIN1) ; also on sheet 1
ETH1_MDI1P: U9.4(MDIP1) ; also on sheet 1
ETH1_MDI2N: U9.7(MDIN2) ; also on sheet 1
ETH1_MDI2P: U9.6(MDIP2) ; also on sheet 1
ETH1_MDI3N: U9.10(MDIN3) ; also on sheet 1
ETH1_MDI3P: U9.9(MDIP3) ; also on sheet 1
ETH1_RSET: R29.2 U9.39(RSET)
ETH2_AVDD10: C162.2 C163.2 C164.2 C173.2 R48.1 U10.3(AVDD10_1) U10.8(AVDD10_2) U10.38(AVDD10_3)
ETH2_AVDD33: C161.2 C165.2 FB4.1 U10.11(AVDD33_1) U10.40(AVDD33_2)
ETH2_DVDD10: C177.2 C178.2 R192.1 U10.21(DVDD10)
ETH2_LED0/CFG_EXT: R44.2 R184.1 U10.32(LED0/CFG_EXT) ; also on sheet 1
ETH2_LED1/CFG_LDO0: R183.1 U10.33(LED1/CFG_LDO0)
ETH2_LED2/CFG_LDO1: R59.2 R190.1 U10.34(LED2/CFG_LDO1) ; also on sheet 1
ETH2_MDI0N: U10.2(MDIN0) ; also on sheet 1
ETH2_MDI0P: U10.1(MDIP0) ; also on sheet 1
ETH2_MDI1N: U10.5(MDIN1) ; also on sheet 1
ETH2_MDI1P: U10.4(MDIP1) ; also on sheet 1
ETH2_MDI2N: U10.7(MDIN2) ; also on sheet 1
ETH2_MDI2P: U10.6(MDIP2) ; also on sheet 1
ETH2_MDI3N: U10.10(MDIN3) ; also on sheet 1
ETH2_MDI3P: U10.9(MDIP3) ; also on sheet 1
ETH2_RSET: R32.2 U10.39(RSET)
G_PERST: Q19.1(G) R157.1 R234.2
GBEPHY1_CLK_XIN: C27.2 U9.36(XTAL_IN) X2.3
GBEPHY1_CLK_XOUT: C23.2 U9.37(XTAL_OUT/_EXT_CLK) X2.1
GBEPHY2_CLK_XIN: C28.2 U10.36(XTAL_IN) X3.3
GBEPHY2_CLK_XOUT: C24.2 U10.37(XTAL_OUT/_EXT_CLK) X3.1
GPIO_IO06: R27.2 ; also on sheet 4
GPIO_IO07: R53.2 ; also on sheet 4
GPIO_IO12: R30.2 ; also on sheet 4
GPIO_IO13/TPM4_CH2: R135.2 U19.2(CTRL) ; also on sheet 4
GPIO_IO16: R58.2 ; also on sheet 4
GPIO_IO17: R61.1 ; also on sheet 4
GPIO_IO24: R114.1 ; also on sheet 4 6
HP_FB: R111.1 U16.B4(HPOUTFB)
HP_J_D: J6.CN R216.1 R217.1
HP_JD: R124.2 R216.2 U16.G1(GPIO5)
HP_L: C112.2 R110.1
HP_MICH: TP4.1 U16.F4(CLKOUT3/GPIO3)
HP_R: C100.2 R104.1
HPOUT_L: C112.1 L18.2 R214.1 U16.B5(HPOUTL)
HPOUT_R: C100.1 L17.2 R215.1 U16.A5(HPOUTR)
I2C3_SCK: R107.2 ; also on sheet 4
I2C3_SCL_CM: P13.1 R106.2 R107.1 R123.2 U27.6(SCL) U28.1(IO1) ; also on sheet 6
I2C3_SDA: R120.2 ; also on sheet 4
I2C3_SDA_CM: P13.3 R119.2 R120.1 R122.2 U27.5(SDA) U28.3(IO2) ; also on sheet 6
INT_DISP: P13.5 R232.1 U28.4(IO3)
J6_CO: J6.CO R218.2
J_HPOUT_L: C199.2 J6.4(L) L18.1
J_HPOUT_R: C194.2 J6.3(R) L17.1
LLINE_IN: C93.2 J5.4(L)
LLINEIN: C92.2 C93.1 U16.E6(IN4L)
LVDS_CLK_N: L15.4 ; also on sheet 4
LVDS_CLK_P: L15.3 ; also on sheet 4
LVDS_CLKN: L15.1 P14.5
LVDS_CLKP: L15.2 P14.3
LVDS_COMP: C133.1 U19.5(COMP)
LVDS_DISP_RESET: P14.17 ; also on sheet 6
LVDS_LED_NEG: C206.1 P14.15 R149.1 R150.1 U19.6(FB)
LVDS_LED_POS: C129.1 C206.2 D2.CATHODE P14.19
LVDS_N0: L19.1 P14.6
LVDS_N1: L14.1 P14.11
LVDS_N2: L20.1 P14.12
LVDS_N3: L21.1 P14.18
LVDS_P0: L19.2 P14.4
LVDS_P1: L14.2 P14.9
LVDS_P2: L20.2 P14.10
LVDS_P3: L21.2 P14.16
LVDS_RESET: R148.1 R149.2 R150.2
LVDS_SW_PWR_IN: C130.1 C131.1 L10.1 R126.2 R135.1 U19.1(IN)
LVDS_TX0_N: L19.4 ; also on sheet 4
LVDS_TX0_P: L19.3 ; also on sheet 4
LVDS_TX1_N: L14.4 ; also on sheet 4
LVDS_TX1_P: L14.3 ; also on sheet 4
LVDS_TX2_N: L20.4 ; also on sheet 4
LVDS_TX2_P: L20.3 ; also on sheet 4
LVDS_TX3_N: L21.4 ; also on sheet 4
LVDS_TX3_P: L21.3 ; also on sheet 4
LVDS_WLD_SW: D2.ANODE L10.2 U19.3(SW)
MICBIAS: C111.1 U16.A4(MICBIAS)
MODEM_AUX: C109.1 P8.24(+3.3V_AUX)
MODEM_RST: R157.2 R235.1 ; also on sheet 6
mux_PCIe_USB_DN: P8.36(USB_D-) ; also on sheet 5
mux_PCIe_USB_DP: P8.38(USB_D+) ; also on sheet 5
PCIe_DISABLEn: R175.1 U6.63(GPIO22/PCIe_DISABLEn)
PERST_L: C138.1 P8.22(PERST#) Q19.3(D) R109.2 R235.2
PHY1_INT: R52.2 R53.1 U9.31(~{INT}/~{PME})
PHY1_RXC: R50.2 U9.27(RXC/PHYAD1)
PHY2_INT: R57.2 R58.1 U10.31(~{INT}/~{PME})
PHY2_RXC: R55.2 U10.27(RXC/PHYAD1)
PMIC_ON_REQ: Q10.5(G2) ; also on sheet 4 6
PMIC_ON_REQn: Q10.2(G1) Q10.3(D2) R209.2
PMIC_STBY_REQ: Q4.5(G) ; also on sheet 4 6
PWR_CTRL: R6.1 R83.1 R100.1 R197.2 U26.4(Y)
PWR_CTRL_IN: Q4.3(D) Q10.6(D1) R197.1 R208.2 U26.2(A)
RF_KILL#: P8.20(W_DISABLE#) R108.2 ; also on sheet 6
RLINE_IN: C190.2 J5.3(R)
RLINEIN: C189.2 C190.1 U16.E7(IN4R)
RS232DB_LED: DS1.ANODE R167.2
SAI1_RXD0: U16.D2(ADCDAT) ; also on sheet 4
SAI1_TXC/CAN1_RX: U16.E1(BCLK) ; also on sheet 4
SAI1_TXD0/CAN1_TX: U16.D1(DACDAT) ; also on sheet 4
SAI1_TXFS: U16.D3(LRCLK) ; also on sheet 4
SD2_CLK: P4.P5(CLK) U22.3(IO2) ; also on sheet 4
SD2_CMD: P4.P3(CMD) U23.6(IO4) ; also on sheet 4
SD2_DATA0: P4.P7(DAT0) U22.1(IO1) ; also on sheet 4
SD2_DATA1: P4.P8(DAT1) U22.6(IO4) ; also on sheet 4
SD2_DATA2: P4.P1(DAT2) U23.1(IO1) ; also on sheet 4
SD2_DATA3: P4.P2(DAT3) U23.4(IO3) ; also on sheet 4
SD2_nCD: P4.P9(CD#) R166.2 ; also on sheet 4
SD3_CLK: R179.1 U6.52(SD_CLK) ; also on sheet 4
SD3_CMD: R182.1 U6.51(SD_CMD) ; also on sheet 4
SD3_DATA0: R237.1 U6.50(SD_DAT0) ; also on sheet 4
SD3_DATA1: R239.1 U6.49(SD_DAT1) ; also on sheet 4
SD3_DATA2: R238.1 U6.48(SD_DAT2) ; also on sheet 4
SD3_DATA3: R240.1 U6.47(SD_DAT3) ; also on sheet 4
SERIAL_VBUSIN: C146.1 P3.1(VBUS) R167.1 U2.4(IO3) U24.7(REGIN) U24.8(VBUS)
SIM_CLK: P7.3(CLK) P8.12(UIM_CLK)
SIM_IO: P7.7(IO) P8.10(UIM_DATA)
SIM_RST: P7.2(RST) P8.14(UIM_RESET)
SIM_VCC: C91.2 P7.1(VCC) P8.8(UIM_PWR)
SIM_VPP: P7.6(VPP) P8.16(UIM_VPP/GPIO42)
TOUCH_RESET: P13.7 U28.6(IO4) ; also on sheet 6
U1_OE: R3.1 U1.6(OE)
UART1_RXD: U1.4(A2) ; also on sheet 4
UART1_TXD: U1.5(A1) ; also on sheet 4
UART2_RXD/GPIO1_IO6/SAI1_MCLK: R112.2 ; also on sheet 4
USBSERIAL_3V45: C3.2 C142.1 C143.1 R1.2 U1.7(VCCB) U24.5(VIO) U24.6(VDD)
USBSERIAL_DN: P3.2(D-) U2.6(IO4) U24.4(DN)
USBSERIAL_DP: P3.3(D+) U2.1(IO1) U24.3(DP)
USBSERIAL_nRST: R1.1 U24.9(RST#)
V_COIN: BH1.1P(+) BH1.3P(+) C96.1 R103.1
V_SOM: C25.1 C29.1 C30.1 C31.1 C34.2 C42.1 C43.1 C46.2 C47.1 C48.1 C186.1 E2.1 R7.2 R42.2 R84.2 R90.1 R101.2 R208.1 R209.1 U26.5(VCC) ; also on sheet 3 4
V_SOM_L: C32.2 C33.2 E2.2 L4.2 R42.1 R187.1
VCOIN: E5.2 R103.2
VDC_IN: C17.1 C20.1 C44.1 C45.1 C59.1 C66.1 C73.1 C74.1 R5.2 R41.2 R82.2 R102.2 U3.8(VIN) U13.8(VIN) U14.8(VIN) U15.8(VIN) ; also on sheet 3
VMIDC: C103.2 U16.C5(VMIDC)
VSD_3V3: R169.2 ; also on sheet 4
VSOM_BOOT: C26.1 U13.2(BOOT)
VSOM_COMP: C55.1 C56.1 U13.6(COMP)
VSOM_COMP_C: C56.2 R88.1
VSOM_EN: R41.1 U13.3(EN)
VSOM_FB: R187.2 R196.1 U13.5(FB)
VSOM_LED: DS3.ANODE R90.2
VSOM_RLIM: R89.1 U13.7(RLIM)
VSOM_SW: C26.2 L4.1 U13.1(SW)
WAKE_BTIN: R176.1 U6.53(GPIO12/HOST_WAKE_BT)
WAKE_WLANIN: R170.1 U6.66(GPIO[15]/TMS)
WL_32XTAL_IN: U12.3(OSCIN) X1.1
WL_32XTAL_OUT: U12.1(OSCOUT) X1.2
WL_CLKEN: R46.2 U12.4(CLKEN)
WL_CLKOUT: R47.1 U12.6(CLKOUT)
WLAN_CONFIG0: R12.2 U6.8(CONFIG_HOST0)
WLAN_CONFIG1: R11.1 U6.9(CONFIG_HOST1)
WLAN_CONFIG2: R18.1 U6.10(CONFIG_HOST2)
WLAN_CONFIG3: R19.1 R20.2 U6.13(CONFIG_HOST3)
WLAN_GPIO14: R63.1 U6.46(GPIO[14]/TCK)
WLANPD: R61.2 R62.2 U6.45(PDn)
XTALI_24M: C95.2 R105.1 R112.1 U16.G7(MCLK/XTI) X4.1
XTALO_24M: C94.2 R105.2 U16.F7(XTO) X4.3

Not connected (* = marked no-connect by the designer): J5 2(AUX) CN* CO*; J6 2(AUX); P3 4(ID)*; P7 4(RSVD4)* 8(RSVD8)*; P8 1(WAKE#/MIC1P)* 3(COEX1/MIC1N)* 5(COEX2/EAR1P)* 6(+1.5V/NC)* 7(CLKREQ#/EAR1N)* 11(REFCLK-/UART_CTS)* 13(REFCLK+/UART_RTS)* 17(RSVD/UART_RXD)* 19(RSVD/UART_TXD)* 23(PER_N0/NC)* 25(PER_P0/NC)* 28(+1.5V/NC)* 30(GPIO9/SMB_CLK)* 31(PET_N0/NC)* 32(GPIO6/SMB_DATA)* 33(PET_P0/NC)* 42(LED_WWAN#)* 44(LED_WLAN#/UART_RI)* 45(RSVD/PCM_CLK)* 46(LED_WPAN#/UART_DTR)* 47(RSVD/PCM_OUT)* 48(+1.5V/NC)* 49(RSVD/PCM_IN)* 51(RSVD/PCM_SYNC)*; P13 4* 6*; RN3 5(RD2)*; U2 3(IO2)* 5(VBUS)*; U6 1(NC1)* 2(NC2)* 3(NC3)* 7(NC4)* 11(GPIO17/_UART_LTE_SOUT/TDO)* 12(GPIO16/_UART_LTE_SIN/TDI)* 14(NC5)* 15(GPIO1)* 16(NC9)* 18(GPIO25)* 19(NC8)* 21(GPIO26)* 22(GPIO27)* 24(ATEST0)* 25(NC7)* 28(GPIO[22]_/NFC/BT_IRQ(O)) 29(PCIE_WAKEn)* 30(PCIE_CLKREQn)* 31(GPIO[21]/PCIE_PERSTn)* 33(PCIE_RCLK_N)* 34(PCIE_RCLK_P)* 36(PCIE_TX_N)* 37(PCIE_TX_P)* 39(PCIE_RX_N)* 40(PCIE_RX_P)* 42(GPIO[0]CLK_REQ)* 43(NC6)* 54(GPIO[10]_/UART_CTSn)* 55(GPIO[8]_/UART_SOUT)* 56(GPIO[9]_/UART_SIN)* 57(GPIO[11]_/_UART_RTSn)* 58(GPIO[7]/PCM_SYNC)* 59(GPIO[4]/PCM_IN)* 60(GPIO[5]/PCM_OUT)* 61(GPIO[6]/PCM_CLK)* 64(GPIO[2]WLAN_LED)* 65(GPIO[3]BT_LED)* 67(NC)* 69(USB_DM)* 70(USB_DP)*; U9 35(CLKOUT)*; U10 35(CLKOUT)*; U16 A1(SPKOUTLP) B2(SPKOUTRP) B3(SPKOUTLN) C3(SPKOUTRN) C4(IN1L)* D4(IN1R)* D5(IN2L)* E5(IN2R)* F5(IN3L)* F6(IN3R)*; U22 4(IO3)*; U23 3(IO2)*; U24 1(RI)* 10(NC)* 11(GPIO3)* 12(GPIO2)* 13(GPIO1)* 14(GPIO0)* 15(SUSPEND#)* 17(SUSPEND)* 18(CTS)* 19(RTS)* 22(DSR)* 23(DTR)* 24(DCD)*

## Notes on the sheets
sheet 8
- GbE PHY1
- Power-on Strapping Pins CFG
- RGMII Power Source
- CFG_EXT
- CFG_LDO[1:0]
- CFG_EXT
- DNP
- External 3.3V (Default)
- 1
- 00
- CFG_LDO1
- DNP
- External 1.8V
- 1
- 10
- CFG_LDO0
- Internal 1.8V
- 0
- 10
- UCM-iMX95
- CONFIG PINS
- PHY ADDRESS = [1,0,0]
- DNP
- PHY support addresses from 00001 to 00111.
  PHY address 0 is a broadcast from the MAC
- DNP
- PLLOFF: Pull-up to disable PLL @ ALDPS mode.
- PLLOFF
- Enable internal delays
- TX delay is enabled
  RX delay is enabled
- Active low
- TXDLY
- DNP
- Active high
- Active low
- RXDLY
- DNP
- PHYADDRESS2
- DNP
- PHYADDRESS1
- PHYADDRESS0
- GbE PHY2
- Power-on Strapping Pins CFG
- RGMII Power Source
- CFG_EXT
- CFG_LDO[1:0]
- CFG_EXT
- DNP
- External 3.3V (Default)
- 1
- 00
- DNP
- CFG_LDO1
- External 1.8V
- 1
- 10
- CFG_LDO0
- Internal 1.8V
- 0
- 10
- CONFIG PINS
- PHY ADDRESS = [1,0,1]
- PHY support addresses from 00001 to 00111.
  PHY address 0 is a broadcast from the MAC
- DNP
- PLLOFF: Pull-up to disable PLL @ ALDPS mode.
- Enable internal delays
- PLLOFF
- TX delay is enabled
  RX delay is enabled
- TXDLY
- DNP
- RXDLY
- DNP
- PHYADDRESS2
- DNP
- Active low
- PHYADDRESS1
- Active high
- Active low
- PHYADDRESS0
- DNP
- DNP
sheet 9
- LVDS LCD Int.
- # 100-Ohm diff pairs
- # 100-Ohm diff pairs
- LVDS/DSI touch panel connector
- LVDS LCD back-light power
- 9.6V/270mA
- DNP
sheet 10
- Serial Console
- USB-to-Serial
- UART LEVEL SHIFTER
- Prevents power draining to board when only
  usb cable is connected
- DEBUG PORT
  (microUSB2.0 Type B)
  UART over USB
- A53 core debug
- USB console
  connection
  indicator
- In
- Out
- DNP
- Micro-SD (bootable)
- DNP
- Carrier board I2C
- EEPROM
- miniPCIe and SIM
- DNP
- DNP
- 3.3V x 2mA = 6.6mW
- DNP
- I2C slave address: 0x54..0x57
- DNP
- int. PU
- DNP
sheet 11
- V_SOM (3A)
- Vout=3.7V
  Iout max = 3A
- Current measure
- DNP
- Vout=0.8*(1+64.9/17.8)=3.72V
- RLIM = 100k => ~4A
- VCC_3V3
- VCC_1V8
- Vout=0.8*(1+56.2/17.8)=3.33V
- Vout=0.8*(1+22.1/17.8)=1.79V
- Vout=3.3V
  Iout max = 3A
- Vout=1.8V
  Iout max = 3A
- RLIM = 100k => ~4A
- RLIM = 100k => ~4A
- DNP
- DNP
- VCC_5V
- PWR_CTRLn
- RTC battery
- Vout=5V
  Iout max = 3A
- Vout=0.8*(1+64.9/12.4)=4.987V
- DNP
- DNP
- RLIM = 100k => ~4A
- DNP
sheet 12
- WiFi/BT 802.11a/b/g/n/ac + Bluetooth 5.0
- Power consumption: <1mA
- According to EM7604 DS, no caps needed on XTAL
- WiFi EVLK
- "001":WiFi-SD/BT-SD
- DNP
sheet 13
- For PCIe module
- Stitching capacitors
- Through hole diameter should be 2.55mm
- 12  Jumper Plugs
sheet 14
- PLUGGED: High
  Removed: Low
- CODEC
- DNP
- DNP
- DNP
- DNP
- i
- o
- SAI1_MCLK
- DNP
- DNP
- DNP
- DNP
